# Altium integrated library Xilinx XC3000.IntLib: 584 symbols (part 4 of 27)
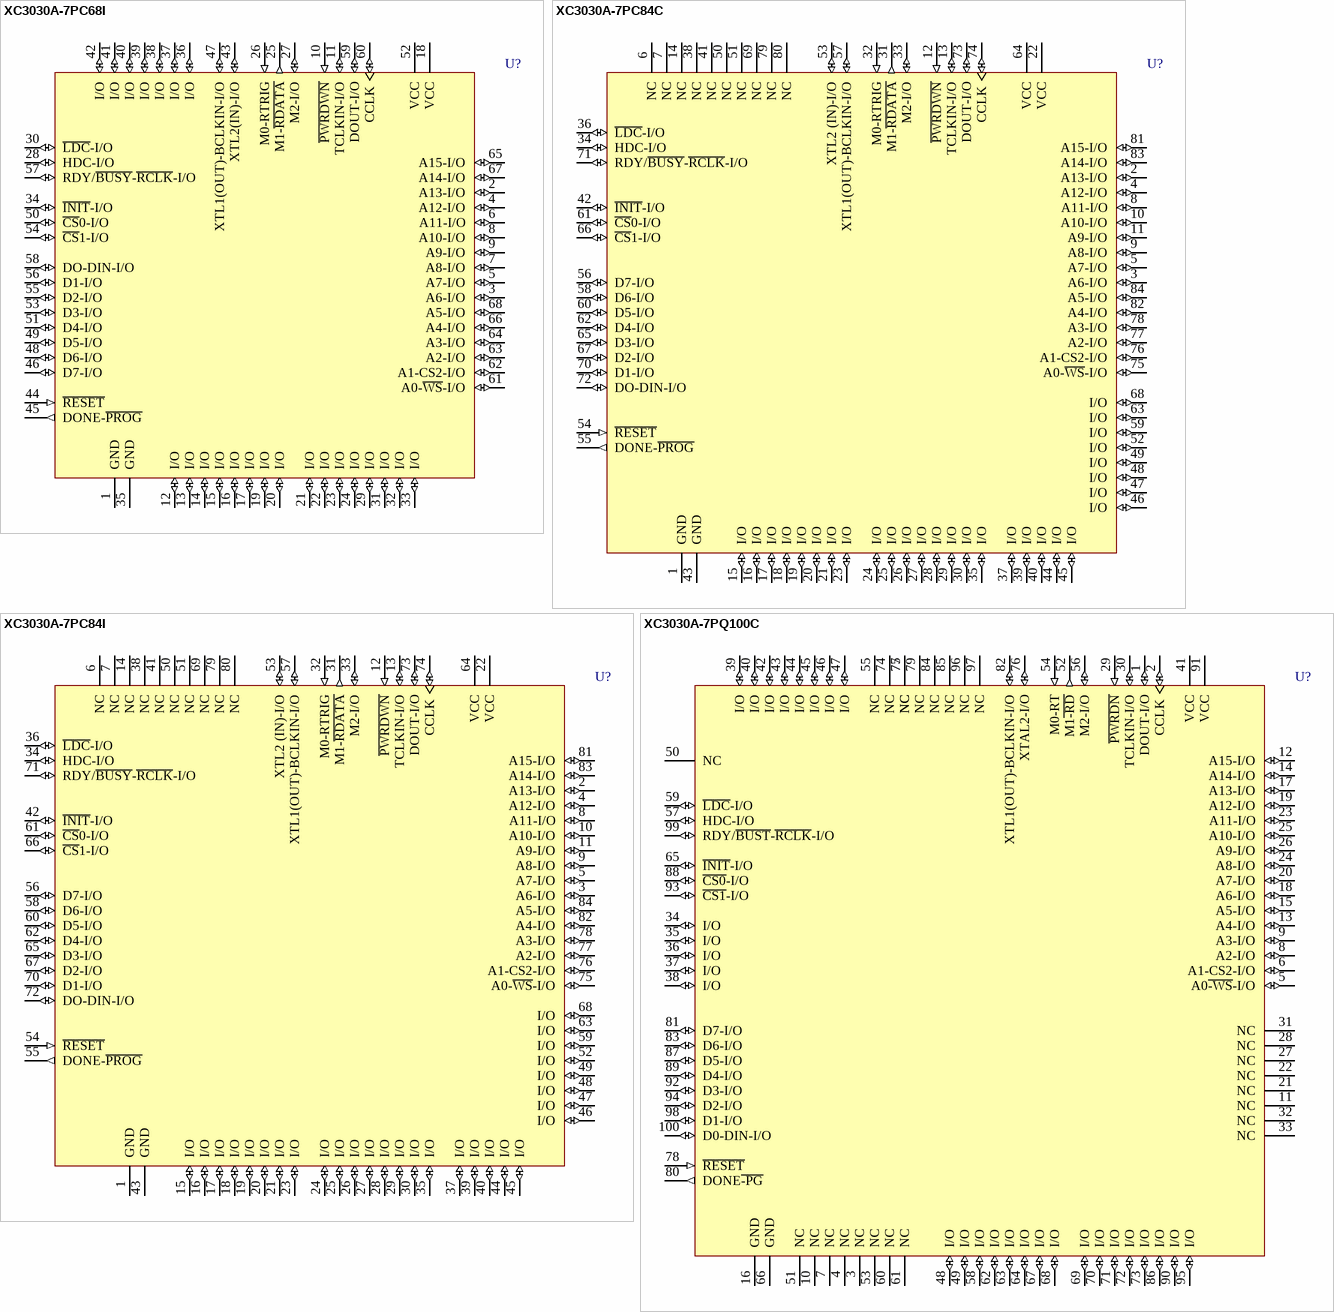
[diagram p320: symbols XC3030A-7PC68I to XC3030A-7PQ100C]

## XC3030A-7PC84C
designator U?
Logic Cell Array with 100 CLBs, with 64 I/O Pins, 84-Pin PLCC, Commercial Grade; ComponentAvailability: Not for New Design
footprint PC84_N (Leaded Chip Carrier, 84-Leads, Body 29.3x29.3mm, Pitch 1.27mm, IPC Medium Density)
footprint PC84_L (Leaded Chip Carrier, 84-Leads, Body 29.3x29.3mm, Pitch 1.27mm, IPC High Density)
footprint PC84_M (Leaded Chip Carrier, 84-Leads, Body 29.3x29.3mm, Pitch 1.27mm, IPC Low Density)
3D model XC3030A-PC84 (84-Pin Plastic Leaded Chip Carrier (PC84))
pins: 1 GND (power), 2 A13-I/O (io), 3 A6-I/O (io), 4 A12-I/O (io), 5 A7-I/O (io), 6 NC, 7 NC, 8 A11-I/O (io), 9 A8-I/O (io), 10 A10-I/O (io), 11 A9-I/O (io), 12 ~{PWRDWN} (in), 13 TCLKIN-I/O (io), 14 NC, 15 I/O (io), 16 I/O (io), 17 I/O (io), 18 I/O (io), 19 I/O (io), 20 I/O (io), 21 I/O (io), 22 VCC (power), 23 I/O (io), 24 I/O (io), 25 I/O (io), 26 I/O (io), 27 I/O (io), 28 I/O (io), 29 I/O (io), 30 I/O (io), 31 M1-~{RDATA} (out), 32 M0-RTRIG (in), 33 M2-I/O (io), 34 HDC-I/O (io), 35 I/O (io), 36 ~{LDC}-I/O (io), 37 I/O (io), 38 NC, 39 I/O (io), 40 I/O (io), 41 NC, 42 ~{INIT}-I/O (io), 43 GND (power), 44 I/O (io), 45 I/O (io), 46 I/O (io), 47 I/O (io), 48 I/O (io), 49 I/O (io), 50 NC, 51 NC, 52 I/O (io), 53 XTL2 (IN)-I/O (io), 54 ~{RESET} (in), 55 DONE-~{PROG} (out), 56 D7-I/O (io), 57 XTL1(OUT)-BCLKIN-I/O (io), 58 D6-I/O (io), 59 I/O (io), 60 D5-I/O (io), 61 ~{CS}0-I/O (io), 62 D4-I/O (io), 63 I/O (io), 64 VCC (power), 65 D3-I/O (io), 66 ~{CS}1-I/O (io), 67 D2-I/O (io), 68 I/O (io), 69 NC, 70 D1-I/O (io), 71 RDY/~{BUSY}-~{RCLK}-I/O (io), 72 DO-DIN-I/O (io), 73 DOUT-I/O (io), 74 CCLK (io), 75 A0-~{WS}-I/O (io), 76 A1-CS2-I/O (io), 77 A2-I/O (io), 78 A3-I/O (io), 79 NC, 80 NC, 81 A15-I/O (io), 82 A4-I/O (io), 83 A14-I/O (io), 84 A5-I/O (io)

## XC3030A-7PC84I
designator U?
Logic Cell Array with 100 CLBs, with 64 I/O Pins, 84-Pin PLCC, Industrial Grade; ComponentAvailability: Not for New Design
footprint PC84_N (Leaded Chip Carrier, 84-Leads, Body 29.3x29.3mm, Pitch 1.27mm, IPC Medium Density)
footprint PC84_L (Leaded Chip Carrier, 84-Leads, Body 29.3x29.3mm, Pitch 1.27mm, IPC High Density)
footprint PC84_M (Leaded Chip Carrier, 84-Leads, Body 29.3x29.3mm, Pitch 1.27mm, IPC Low Density)
3D model XC3030A-PC84 (84-Pin Plastic Leaded Chip Carrier (PC84))
pins: 1 GND (power), 2 A13-I/O (io), 3 A6-I/O (io), 4 A12-I/O (io), 5 A7-I/O (io), 6 NC, 7 NC, 8 A11-I/O (io), 9 A8-I/O (io), 10 A10-I/O (io), 11 A9-I/O (io), 12 ~{PWRDWN} (in), 13 TCLKIN-I/O (io), 14 NC, 15 I/O (io), 16 I/O (io), 17 I/O (io), 18 I/O (io), 19 I/O (io), 20 I/O (io), 21 I/O (io), 22 VCC (power), 23 I/O (io), 24 I/O (io), 25 I/O (io), 26 I/O (io), 27 I/O (io), 28 I/O (io), 29 I/O (io), 30 I/O (io), 31 M1-~{RDATA} (out), 32 M0-RTRIG (in), 33 M2-I/O (io), 34 HDC-I/O (io), 35 I/O (io), 36 ~{LDC}-I/O (io), 37 I/O (io), 38 NC, 39 I/O (io), 40 I/O (io), 41 NC, 42 ~{INIT}-I/O (io), 43 GND (power), 44 I/O (io), 45 I/O (io), 46 I/O (io), 47 I/O (io), 48 I/O (io), 49 I/O (io), 50 NC, 51 NC, 52 I/O (io), 53 XTL2 (IN)-I/O (io), 54 ~{RESET} (in), 55 DONE-~{PROG} (out), 56 D7-I/O (io), 57 XTL1(OUT)-BCLKIN-I/O (io), 58 D6-I/O (io), 59 I/O (io), 60 D5-I/O (io), 61 ~{CS}0-I/O (io), 62 D4-I/O (io), 63 I/O (io), 64 VCC (power), 65 D3-I/O (io), 66 ~{CS}1-I/O (io), 67 D2-I/O (io), 68 I/O (io), 69 NC, 70 D1-I/O (io), 71 RDY/~{BUSY}-~{RCLK}-I/O (io), 72 DO-DIN-I/O (io), 73 DOUT-I/O (io), 74 CCLK (io), 75 A0-~{WS}-I/O (io), 76 A1-CS2-I/O (io), 77 A2-I/O (io), 78 A3-I/O (io), 79 NC, 80 NC, 81 A15-I/O (io), 82 A4-I/O (io), 83 A14-I/O (io), 84 A5-I/O (io)

## XC3030A-7PQ100C
designator U?
Logic Cell Array with 100 CLBs, with 64 I/O Pins, 100-Pin PQFP, Commercial Grade; ComponentAvailability: Not for New Design
footprint PQ100_N (QFP, 100-Leads, Body 20x14mm, Pitch 0.65mm, IPC Medium Density)
footprint PQ100_L (QFP, 100-Leads, Body 20x14mm, Pitch 0.65mm, IPC High Density)
footprint PQ100_M (QFP, 100-Leads, Body 20x14mm, Pitch 0.65mm, IPC Low Density)
3D model XC3030A-PQ100 (100-Pin Plastic Quad Flat Pack (PQ100))
pins: 1 DOUT-I/O (io), 2 CCLK (io), 3 NC, 4 NC, 5 A0~{-WS}-I/O (io), 6 A1-CS2-I/O (io), 7 NC, 8 A2-I/O (io), 9 A3-I/O (io), 10 NC, 11 NC, 12 A15-I/O (io), 13 A4-I/O (io), 14 A14-I/O (io), 15 A5-I/O (io), 16 GND (power), 17 A13-I/O (io), 18 A6-I/O (io), 19 A12-I/O (io), 20 A7-I/O (io), 21 NC, 22 NC, 23 A11-I/O (io), 24 A8-I/O (io), 25 A10-I/O (io), 26 A9-I/O (io), 27 NC, 28 NC, 29 ~{PWRDN} (in), 30 TCLKIN-I/O (io), 31 NC, 32 NC, 33 NC, 34 I/O (io), 35 I/O (io), 36 I/O (io), 37 I/O (io), 38 I/O (io), 39 I/O (io), 40 I/O (io), 41 VCC (power), 42 I/O (io), 43 I/O (io), 44 I/O (io), 45 I/O (io), 46 I/O (io), 47 I/O (io), 48 I/O (io), 49 I/O (io), 50 NC, 51 NC, 52 M1~{-RD} (out), 53 NC, 54 M0-RT (in), 55 NC, 56 M2-I/O (io), 57 HDC-I/O (io), 58 I/O (io), 59 ~{LDC}-I/O (io), 60 NC, 61 NC, 62 I/O (io), 63 I/O (io), 64 I/O (io), 65 ~{INIT}-I/O (io), 66 GND (power), 67 I/O (io), 68 I/O (io), 69 I/O (io), 70 I/O (io), 71 I/O (io), 72 I/O (io), 73 I/O (io), 74 NC, 75 NC, 76 XTAL2-I/O (io), 77 NC, 78 ~{RESET} (in), 79 NC, 80 DONE~{-PG} (out), 81 D7-I/O (io), 82 XTL1(OUT)-BCLKIN-I/O (io), 83 D6-I/O (io), 84 NC, 85 NC, 86 I/O (io), 87 D5-I/O (io), 88 ~{CS0}-I/O (io), 89 D4-I/O (io), 90 I/O (io), 91 VCC (power), 92 D3-I/O (io), 93 ~{CS1}-I/O (io), 94 D2-I/O (io), 95 I/O (io), 96 NC, 97 NC, 98 D1-I/O (io), 99 RDY/~{BUST}-~{RCLK}-I/O (io), 100 D0-DIN-I/O (io)

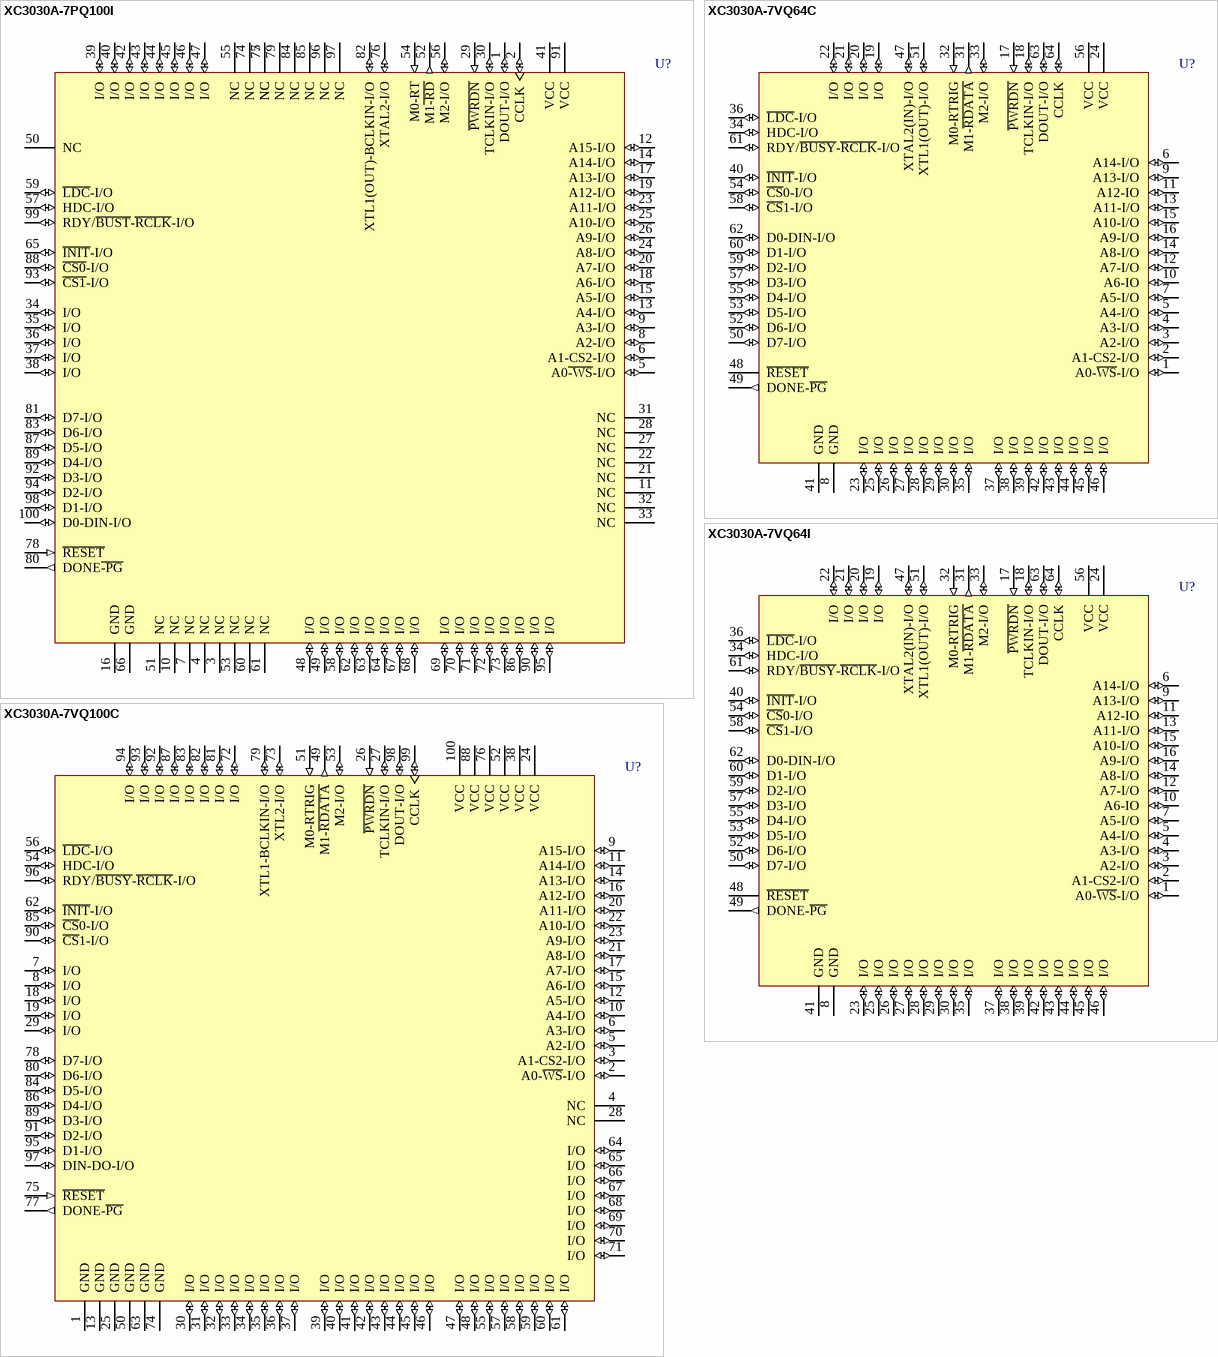
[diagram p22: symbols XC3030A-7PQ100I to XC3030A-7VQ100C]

## XC3030A-7PQ100I
designator U?
Logic Cell Array with 100 CLBs, with 64 I/O Pins, 100-Pin PQFP, Industrial Grade; ComponentAvailability: Not for New Design
footprint PQ100_N (QFP, 100-Leads, Body 20x14mm, Pitch 0.65mm, IPC Medium Density)
footprint PQ100_L (QFP, 100-Leads, Body 20x14mm, Pitch 0.65mm, IPC High Density)
footprint PQ100_M (QFP, 100-Leads, Body 20x14mm, Pitch 0.65mm, IPC Low Density)
3D model XC3030A-PQ100 (100-Pin Plastic Quad Flat Pack (PQ100))
pins: 1 DOUT-I/O (io), 2 CCLK (io), 3 NC, 4 NC, 5 A0~{-WS}-I/O (io), 6 A1-CS2-I/O (io), 7 NC, 8 A2-I/O (io), 9 A3-I/O (io), 10 NC, 11 NC, 12 A15-I/O (io), 13 A4-I/O (io), 14 A14-I/O (io), 15 A5-I/O (io), 16 GND (power), 17 A13-I/O (io), 18 A6-I/O (io), 19 A12-I/O (io), 20 A7-I/O (io), 21 NC, 22 NC, 23 A11-I/O (io), 24 A8-I/O (io), 25 A10-I/O (io), 26 A9-I/O (io), 27 NC, 28 NC, 29 ~{PWRDN} (in), 30 TCLKIN-I/O (io), 31 NC, 32 NC, 33 NC, 34 I/O (io), 35 I/O (io), 36 I/O (io), 37 I/O (io), 38 I/O (io), 39 I/O (io), 40 I/O (io), 41 VCC (power), 42 I/O (io), 43 I/O (io), 44 I/O (io), 45 I/O (io), 46 I/O (io), 47 I/O (io), 48 I/O (io), 49 I/O (io), 50 NC, 51 NC, 52 M1~{-RD} (out), 53 NC, 54 M0-RT (in), 55 NC, 56 M2-I/O (io), 57 HDC-I/O (io), 58 I/O (io), 59 ~{LDC}-I/O (io), 60 NC, 61 NC, 62 I/O (io), 63 I/O (io), 64 I/O (io), 65 ~{INIT}-I/O (io), 66 GND (power), 67 I/O (io), 68 I/O (io), 69 I/O (io), 70 I/O (io), 71 I/O (io), 72 I/O (io), 73 I/O (io), 74 NC, 75 NC, 76 XTAL2-I/O (io), 77 NC, 78 ~{RESET} (in), 79 NC, 80 DONE~{-PG} (out), 81 D7-I/O (io), 82 XTL1(OUT)-BCLKIN-I/O (io), 83 D6-I/O (io), 84 NC, 85 NC, 86 I/O (io), 87 D5-I/O (io), 88 ~{CS0}-I/O (io), 89 D4-I/O (io), 90 I/O (io), 91 VCC (power), 92 D3-I/O (io), 93 ~{CS1}-I/O (io), 94 D2-I/O (io), 95 I/O (io), 96 NC, 97 NC, 98 D1-I/O (io), 99 RDY/~{BUST}-~{RCLK}-I/O (io), 100 D0-DIN-I/O (io)

## XC3030A-7VQ64C
designator U?
Logic Cell Array with 100 CLBs, with 54 I/O Pins, 64-Pin VQFP, Commercial Grade; ComponentAvailability: Not for New Design
footprint VQ64_N (Thin QFP, 64-Leads, Body 10x10mm, Pitch 0.5mm, IPC Medium Density)
footprint VQ64_L (Thin QFP, 64-Leads, Body 10x10mm, Pitch 0.5mm, IPC High Density)
footprint VQ64_M (Thin QFP, 64-Leads, Body 10x10mm, Pitch 0.5mm, IPC Low Density)
3D model XC3030A-VQ64 (64-Pin Very Thin Quad Flat Pack (VQ64))
pins: 1 A0-~{WS}-I/O (io), 2 A1-CS2-I/O (io), 3 A2-I/O (io), 4 A3-I/O (io), 5 A4-I/O (io), 6 A14-I/O (io), 7 A5-I/O (io), 8 GND (power), 9 A13-I/O (io), 10 A6-IO (io), 11 A12-IO (io), 12 A7-I/O (io), 13 A11-I/O (io), 14 A8-I/O (io), 15 A10-I/O (io), 16 A9-I/O (io), 17 ~{PWRDN} (in), 18 TCLKIN-I/O (io), 19 I/O (io), 20 I/O (io), 21 I/O (io), 22 I/O (io), 23 I/O (io), 24 VCC (power), 25 I/O (io), 26 I/O (io), 27 I/O (io), 28 I/O (io), 29 I/O (io), 30 I/O (io), 31 M1-~{RDATA} (out), 32 M0-RTRIG (in), 33 M2-I/O (io), 34 HDC-I/O (io), 35 I/O (io), 36 ~{LDC}-I/O (io), 37 I/O (io), 38 I/O (io), 39 I/O (io), 40 ~{INIT}-I/O (io), 41 GND (power), 42 I/O (io), 43 I/O (io), 44 I/O (io), 45 I/O (io), 46 I/O (io), 47 XTAL2(IN)-I/O (io), 48 ~{RESET}, 49 DONE-~{PG} (out), 50 D7-I/O (io), 51 XTL1(OUT)-I/O (io), 52 D6-I/O (io), 53 D5-I/O (io), 54 ~{CS}0-I/O (io), 55 D4-I/O (io), 56 VCC (power), 57 D3-I/O (io), 58 ~{CS}1-I/O (io), 59 D2-I/O (io), 60 D1-I/O (io), 61 RDY/~{BUSY}-~{RCLK}-I/O (io), 62 D0-DIN-I/O (io), 63 DOUT-I/O (io), 64 CCLK (io)

## XC3030A-7VQ64I
designator U?
Logic Cell Array with 100 CLBs, with 54 I/O Pins, 64-Pin VQFP, Industrial Grade; ComponentAvailability: Not for New Design
footprint VQ64_N (Thin QFP, 64-Leads, Body 10x10mm, Pitch 0.5mm, IPC Medium Density)
footprint VQ64_L (Thin QFP, 64-Leads, Body 10x10mm, Pitch 0.5mm, IPC High Density)
footprint VQ64_M (Thin QFP, 64-Leads, Body 10x10mm, Pitch 0.5mm, IPC Low Density)
3D model XC3030A-VQ64 (64-Pin Very Thin Quad Flat Pack (VQ64))
pins: 1 A0-~{WS}-I/O (io), 2 A1-CS2-I/O (io), 3 A2-I/O (io), 4 A3-I/O (io), 5 A4-I/O (io), 6 A14-I/O (io), 7 A5-I/O (io), 8 GND (power), 9 A13-I/O (io), 10 A6-IO (io), 11 A12-IO (io), 12 A7-I/O (io), 13 A11-I/O (io), 14 A8-I/O (io), 15 A10-I/O (io), 16 A9-I/O (io), 17 ~{PWRDN} (in), 18 TCLKIN-I/O (io), 19 I/O (io), 20 I/O (io), 21 I/O (io), 22 I/O (io), 23 I/O (io), 24 VCC (power), 25 I/O (io), 26 I/O (io), 27 I/O (io), 28 I/O (io), 29 I/O (io), 30 I/O (io), 31 M1-~{RDATA} (out), 32 M0-RTRIG (in), 33 M2-I/O (io), 34 HDC-I/O (io), 35 I/O (io), 36 ~{LDC}-I/O (io), 37 I/O (io), 38 I/O (io), 39 I/O (io), 40 ~{INIT}-I/O (io), 41 GND (power), 42 I/O (io), 43 I/O (io), 44 I/O (io), 45 I/O (io), 46 I/O (io), 47 XTAL2(IN)-I/O (io), 48 ~{RESET}, 49 DONE-~{PG} (out), 50 D7-I/O (io), 51 XTL1(OUT)-I/O (io), 52 D6-I/O (io), 53 D5-I/O (io), 54 ~{CS}0-I/O (io), 55 D4-I/O (io), 56 VCC (power), 57 D3-I/O (io), 58 ~{CS}1-I/O (io), 59 D2-I/O (io), 60 D1-I/O (io), 61 RDY/~{BUSY}-~{RCLK}-I/O (io), 62 D0-DIN-I/O (io), 63 DOUT-I/O (io), 64 CCLK (io)

## XC3030A-7VQ100C
designator U?
Logic Cell Array with 100 CLBs, with 80 I/O Pins, 100-Pin VQFP, Commercial Grade; ComponentAvailability: Not for New Design
footprint VQ100_N (Thin QFP, 100-Leads, Body 14x14mm, Pitch 0.5mm, IPC Medium Density)
footprint VQ100_L (Thin QFP, 100-Leads, Body 14x14mm, Pitch 0.5mm, IPC High Density)
footprint VQ100_M (Thin QFP, 100-Leads, Body 14x14mm, Pitch 0.5mm, IPC Low Density)
3D model XC3030A-VQ100 (100-Pin Very Thin Quad Flat Pack (VQ100))
pins: 1 GND (power), 2 A0-~{WS}-I/O (io), 3 A1-CS2-I/O (io), 4 NC, 5 A2-I/O (io), 6 A3-I/O (io), 7 I/O (io), 8 I/O (io), 9 A15-I/O (io), 10 A4-I/O (io), 11 A14-I/O (io), 12 A5-I/O (io), 13 GND (power), 14 A13-I/O (io), 15 A6-I/O (io), 16 A12-I/O (io), 17 A7-I/O (io), 18 I/O (io), 19 I/O (io), 20 A11-I/O (io), 21 A8-I/O (io), 22 A10-I/O (io), 23 A9-I/O (io), 24 VCC (power), 25 GND (power), 26 ~{PWRDN} (in), 27 TCLKIN-I/O (io), 28 NC, 29 I/O (io), 30 I/O (io), 31 I/O (io), 32 I/O (io), 33 I/O (io), 34 I/O (io), 35 I/O (io), 36 I/O (io), 37 I/O (io), 38 VCC (power), 39 I/O (io), 40 I/O (io), 41 I/O (io), 42 I/O (io), 43 I/O (io), 44 I/O (io), 45 I/O (io), 46 I/O (io), 47 I/O (io), 48 I/O (io), 49 M1-~{RDATA} (out), 50 GND (power), 51 M0-RTRIG (in), 52 VCC (power), 53 M2-I/O (io), 54 HDC-I/O (io), 55 I/O (io), 56 ~{LDC}-I/O (io), 57 I/O (io), 58 I/O (io), 59 I/O (io), 60 I/O (io), 61 I/O (io), 62 ~{INIT}-I/O (io), 63 GND (power), 64 I/O (io), 65 I/O (io), 66 I/O (io), 67 I/O (io), 68 I/O (io), 69 I/O (io), 70 I/O (io), 71 I/O (io), 72 I/O (io), 73 XTL2-I/O (io), 74 GND (power), 75 ~{RESET} (in), 76 VCC (power), 77 DONE-~{PG} (out), 78 D7-I/O (io), 79 XTL1-BCLKIN-I/O (io), 80 D6-I/O (io), 81 I/O (io), 82 I/O (io), 83 I/O (io), 84 D5-I/O (io), 85 ~{CS}0-I/O (io), 86 D4-I/O (io), 87 I/O (io), 88 VCC (power), 89 D3-I/O (io), 90 ~{CS}1-I/O (io), 91 D2-I/O (io), 92 I/O (io), 93 I/O (io), 94 I/O (io), 95 D1-I/O (io), 96 RDY/~{BUSY}-~{RCLK}-I/O (io), 97 DIN-DO-I/O (io), 98 DOUT-I/O (io), 99 CCLK (io), 100 VCC (power)

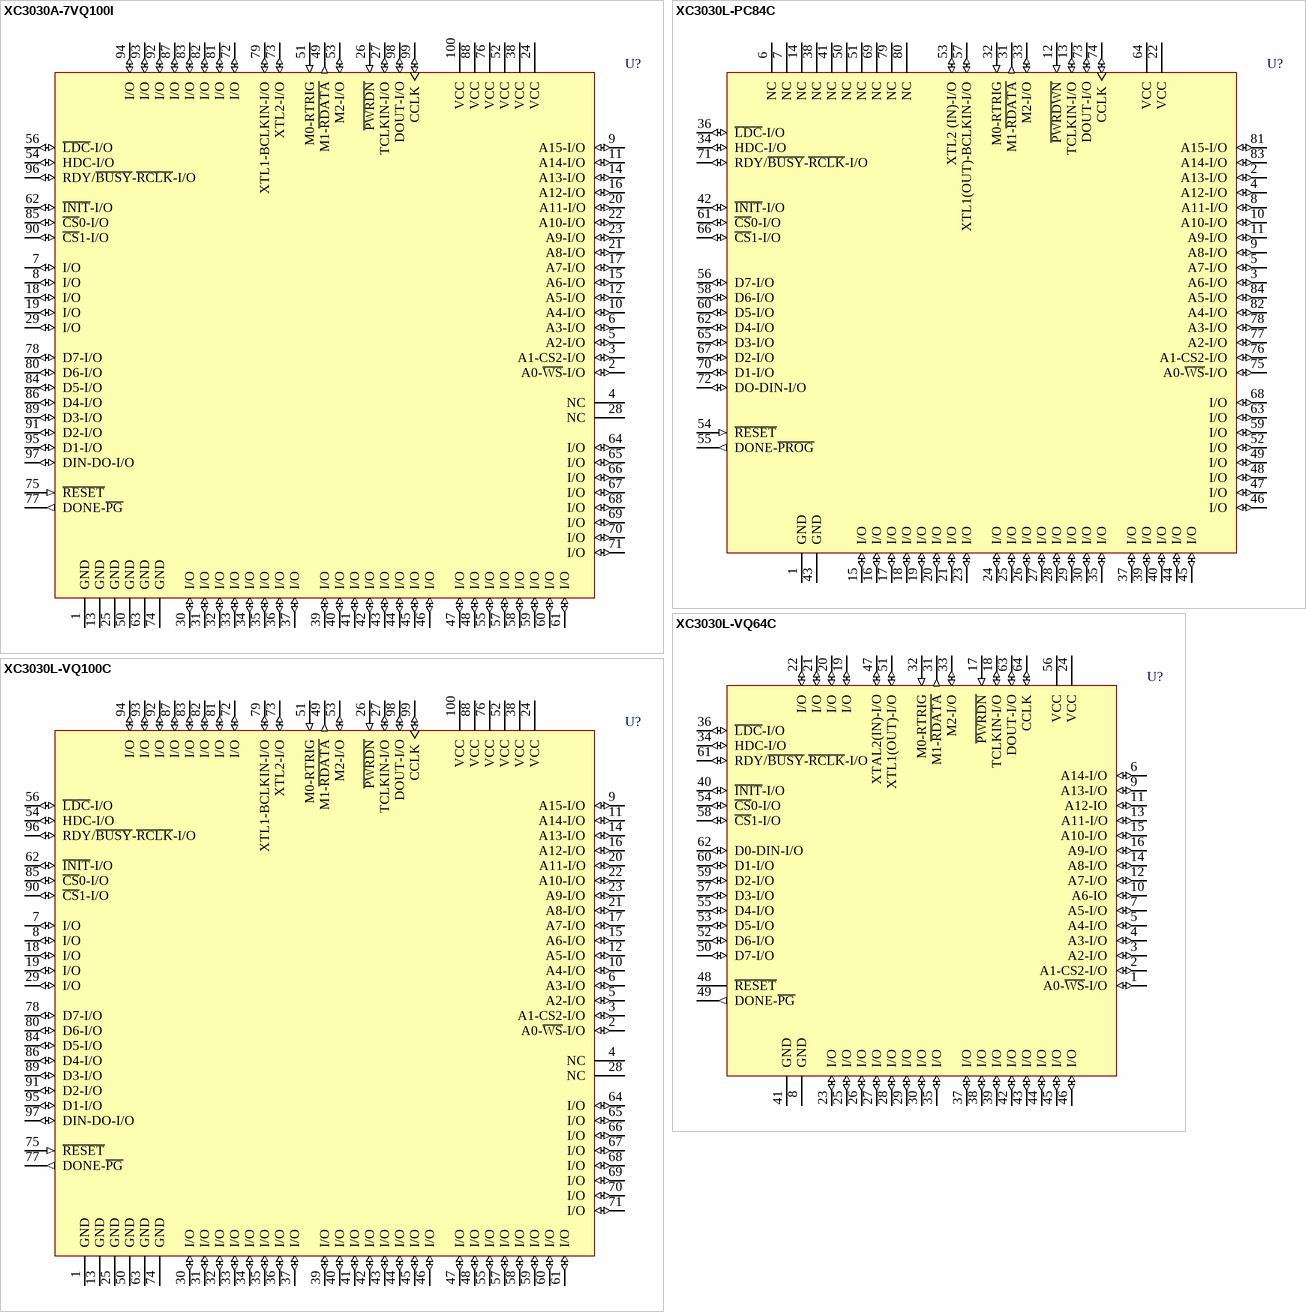
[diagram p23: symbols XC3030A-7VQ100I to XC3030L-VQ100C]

## XC3030A-7VQ100I
designator U?
Logic Cell Array with 100 CLBs, with 80 I/O Pins, 100-Pin VQFP, Industrial Grade; ComponentAvailability: Not for New Design
footprint VQ100_N (Thin QFP, 100-Leads, Body 14x14mm, Pitch 0.5mm, IPC Medium Density)
footprint VQ100_L (Thin QFP, 100-Leads, Body 14x14mm, Pitch 0.5mm, IPC High Density)
footprint VQ100_M (Thin QFP, 100-Leads, Body 14x14mm, Pitch 0.5mm, IPC Low Density)
3D model XC3030A-VQ100 (100-Pin Very Thin Quad Flat Pack (VQ100))
pins: 1 GND (power), 2 A0-~{WS}-I/O (io), 3 A1-CS2-I/O (io), 4 NC, 5 A2-I/O (io), 6 A3-I/O (io), 7 I/O (io), 8 I/O (io), 9 A15-I/O (io), 10 A4-I/O (io), 11 A14-I/O (io), 12 A5-I/O (io), 13 GND (power), 14 A13-I/O (io), 15 A6-I/O (io), 16 A12-I/O (io), 17 A7-I/O (io), 18 I/O (io), 19 I/O (io), 20 A11-I/O (io), 21 A8-I/O (io), 22 A10-I/O (io), 23 A9-I/O (io), 24 VCC (power), 25 GND (power), 26 ~{PWRDN} (in), 27 TCLKIN-I/O (io), 28 NC, 29 I/O (io), 30 I/O (io), 31 I/O (io), 32 I/O (io), 33 I/O (io), 34 I/O (io), 35 I/O (io), 36 I/O (io), 37 I/O (io), 38 VCC (power), 39 I/O (io), 40 I/O (io), 41 I/O (io), 42 I/O (io), 43 I/O (io), 44 I/O (io), 45 I/O (io), 46 I/O (io), 47 I/O (io), 48 I/O (io), 49 M1-~{RDATA} (out), 50 GND (power), 51 M0-RTRIG (in), 52 VCC (power), 53 M2-I/O (io), 54 HDC-I/O (io), 55 I/O (io), 56 ~{LDC}-I/O (io), 57 I/O (io), 58 I/O (io), 59 I/O (io), 60 I/O (io), 61 I/O (io), 62 ~{INIT}-I/O (io), 63 GND (power), 64 I/O (io), 65 I/O (io), 66 I/O (io), 67 I/O (io), 68 I/O (io), 69 I/O (io), 70 I/O (io), 71 I/O (io), 72 I/O (io), 73 XTL2-I/O (io), 74 GND (power), 75 ~{RESET} (in), 76 VCC (power), 77 DONE-~{PG} (out), 78 D7-I/O (io), 79 XTL1-BCLKIN-I/O (io), 80 D6-I/O (io), 81 I/O (io), 82 I/O (io), 83 I/O (io), 84 D5-I/O (io), 85 ~{CS}0-I/O (io), 86 D4-I/O (io), 87 I/O (io), 88 VCC (power), 89 D3-I/O (io), 90 ~{CS}1-I/O (io), 91 D2-I/O (io), 92 I/O (io), 93 I/O (io), 94 I/O (io), 95 D1-I/O (io), 96 RDY/~{BUSY}-~{RCLK}-I/O (io), 97 DIN-DO-I/O (io), 98 DOUT-I/O (io), 99 CCLK (io), 100 VCC (power)

## XC3030L-PC84C
designator U?
Logic Cell Array with 100 CLBs, with 64 I/O Pins, 84-Pin PLCC, Commercial Grade; ComponentAvailability: Not for New Design
footprint PC84_N (Leaded Chip Carrier, 84-Leads, Body 29.3x29.3mm, Pitch 1.27mm, IPC Medium Density)
footprint PC84_L (Leaded Chip Carrier, 84-Leads, Body 29.3x29.3mm, Pitch 1.27mm, IPC High Density)
footprint PC84_M (Leaded Chip Carrier, 84-Leads, Body 29.3x29.3mm, Pitch 1.27mm, IPC Low Density)
3D model XC3030L-PC84 (84-Pin Plastic Leaded Chip Carrier (PC84))
pins: 1 GND (power), 2 A13-I/O (io), 3 A6-I/O (io), 4 A12-I/O (io), 5 A7-I/O (io), 6 NC, 7 NC, 8 A11-I/O (io), 9 A8-I/O (io), 10 A10-I/O (io), 11 A9-I/O (io), 12 ~{PWRDWN} (in), 13 TCLKIN-I/O (io), 14 NC, 15 I/O (io), 16 I/O (io), 17 I/O (io), 18 I/O (io), 19 I/O (io), 20 I/O (io), 21 I/O (io), 22 VCC (power), 23 I/O (io), 24 I/O (io), 25 I/O (io), 26 I/O (io), 27 I/O (io), 28 I/O (io), 29 I/O (io), 30 I/O (io), 31 M1-~{RDATA} (out), 32 M0-RTRIG (in), 33 M2-I/O (io), 34 HDC-I/O (io), 35 I/O (io), 36 ~{LDC}-I/O (io), 37 I/O (io), 38 NC, 39 I/O (io), 40 I/O (io), 41 NC, 42 ~{INIT}-I/O (io), 43 GND (power), 44 I/O (io), 45 I/O (io), 46 I/O (io), 47 I/O (io), 48 I/O (io), 49 I/O (io), 50 NC, 51 NC, 52 I/O (io), 53 XTL2 (IN)-I/O (io), 54 ~{RESET} (in), 55 DONE-~{PROG} (out), 56 D7-I/O (io), 57 XTL1(OUT)-BCLKIN-I/O (io), 58 D6-I/O (io), 59 I/O (io), 60 D5-I/O (io), 61 ~{CS}0-I/O (io), 62 D4-I/O (io), 63 I/O (io), 64 VCC (power), 65 D3-I/O (io), 66 ~{CS}1-I/O (io), 67 D2-I/O (io), 68 I/O (io), 69 NC, 70 D1-I/O (io), 71 RDY/~{BUSY}-~{RCLK}-I/O (io), 72 DO-DIN-I/O (io), 73 DOUT-I/O (io), 74 CCLK (io), 75 A0-~{WS}-I/O (io), 76 A1-CS2-I/O (io), 77 A2-I/O (io), 78 A3-I/O (io), 79 NC, 80 NC, 81 A15-I/O (io), 82 A4-I/O (io), 83 A14-I/O (io), 84 A5-I/O (io)

## XC3030L-VQ64C
designator U?
Logic Cell Array with 100 CLBs, with 54 I/O Pins, 64-Pin VQFP, Commercial Grade; ComponentAvailability: Not for New Design
footprint VQ64_N (Thin QFP, 64-Leads, Body 10x10mm, Pitch 0.5mm, IPC Medium Density)
footprint VQ64_L (Thin QFP, 64-Leads, Body 10x10mm, Pitch 0.5mm, IPC High Density)
footprint VQ64_M (Thin QFP, 64-Leads, Body 10x10mm, Pitch 0.5mm, IPC Low Density)
3D model XC3030L-VQ64 (64-Pin Very Thin Quad Flat Pack (VQ64))
pins: 1 A0-~{WS}-I/O (io), 2 A1-CS2-I/O (io), 3 A2-I/O (io), 4 A3-I/O (io), 5 A4-I/O (io), 6 A14-I/O (io), 7 A5-I/O (io), 8 GND (power), 9 A13-I/O (io), 10 A6-IO (io), 11 A12-IO (io), 12 A7-I/O (io), 13 A11-I/O (io), 14 A8-I/O (io), 15 A10-I/O (io), 16 A9-I/O (io), 17 ~{PWRDN} (in), 18 TCLKIN-I/O (io), 19 I/O (io), 20 I/O (io), 21 I/O (io), 22 I/O (io), 23 I/O (io), 24 VCC (power), 25 I/O (io), 26 I/O (io), 27 I/O (io), 28 I/O (io), 29 I/O (io), 30 I/O (io), 31 M1-~{RDATA} (out), 32 M0-RTRIG (in), 33 M2-I/O (io), 34 HDC-I/O (io), 35 I/O (io), 36 ~{LDC}-I/O (io), 37 I/O (io), 38 I/O (io), 39 I/O (io), 40 ~{INIT}-I/O (io), 41 GND (power), 42 I/O (io), 43 I/O (io), 44 I/O (io), 45 I/O (io), 46 I/O (io), 47 XTAL2(IN)-I/O (io), 48 ~{RESET}, 49 DONE-~{PG} (out), 50 D7-I/O (io), 51 XTL1(OUT)-I/O (io), 52 D6-I/O (io), 53 D5-I/O (io), 54 ~{CS}0-I/O (io), 55 D4-I/O (io), 56 VCC (power), 57 D3-I/O (io), 58 ~{CS}1-I/O (io), 59 D2-I/O (io), 60 D1-I/O (io), 61 RDY/~{BUSY}-~{RCLK}-I/O (io), 62 D0-DIN-I/O (io), 63 DOUT-I/O (io), 64 CCLK (io)

## XC3030L-VQ100C
designator U?
Logic Cell Array with 100 CLBs, with 80 I/O Pins, 100-Pin VQFP, Commercial Grade; ComponentAvailability: Not for New Design
footprint VQ100_N (Thin QFP, 100-Leads, Body 14x14mm, Pitch 0.5mm, IPC Medium Density)
footprint VQ100_L (Thin QFP, 100-Leads, Body 14x14mm, Pitch 0.5mm, IPC High Density)
footprint VQ100_M (Thin QFP, 100-Leads, Body 14x14mm, Pitch 0.5mm, IPC Low Density)
3D model XC3030L-VQ100 (100-Pin Very Thin Quad Flat Pack (VQ100))
pins: 1 GND (power), 2 A0-~{WS}-I/O (io), 3 A1-CS2-I/O (io), 4 NC, 5 A2-I/O (io), 6 A3-I/O (io), 7 I/O (io), 8 I/O (io), 9 A15-I/O (io), 10 A4-I/O (io), 11 A14-I/O (io), 12 A5-I/O (io), 13 GND (power), 14 A13-I/O (io), 15 A6-I/O (io), 16 A12-I/O (io), 17 A7-I/O (io), 18 I/O (io), 19 I/O (io), 20 A11-I/O (io), 21 A8-I/O (io), 22 A10-I/O (io), 23 A9-I/O (io), 24 VCC (power), 25 GND (power), 26 ~{PWRDN} (in), 27 TCLKIN-I/O (io), 28 NC, 29 I/O (io), 30 I/O (io), 31 I/O (io), 32 I/O (io), 33 I/O (io), 34 I/O (io), 35 I/O (io), 36 I/O (io), 37 I/O (io), 38 VCC (power), 39 I/O (io), 40 I/O (io), 41 I/O (io), 42 I/O (io), 43 I/O (io), 44 I/O (io), 45 I/O (io), 46 I/O (io), 47 I/O (io), 48 I/O (io), 49 M1-~{RDATA} (out), 50 GND (power), 51 M0-RTRIG (in), 52 VCC (power), 53 M2-I/O (io), 54 HDC-I/O (io), 55 I/O (io), 56 ~{LDC}-I/O (io), 57 I/O (io), 58 I/O (io), 59 I/O (io), 60 I/O (io), 61 I/O (io), 62 ~{INIT}-I/O (io), 63 GND (power), 64 I/O (io), 65 I/O (io), 66 I/O (io), 67 I/O (io), 68 I/O (io), 69 I/O (io), 70 I/O (io), 71 I/O (io), 72 I/O (io), 73 XTL2-I/O (io), 74 GND (power), 75 ~{RESET} (in), 76 VCC (power), 77 DONE-~{PG} (out), 78 D7-I/O (io), 79 XTL1-BCLKIN-I/O (io), 80 D6-I/O (io), 81 I/O (io), 82 I/O (io), 83 I/O (io), 84 D5-I/O (io), 85 ~{CS}0-I/O (io), 86 D4-I/O (io), 87 I/O (io), 88 VCC (power), 89 D3-I/O (io), 90 ~{CS}1-I/O (io), 91 D2-I/O (io), 92 I/O (io), 93 I/O (io), 94 I/O (io), 95 D1-I/O (io), 96 RDY/~{BUSY}-~{RCLK}-I/O (io), 97 DIN-DO-I/O (io), 98 DOUT-I/O (io), 99 CCLK (io), 100 VCC (power)

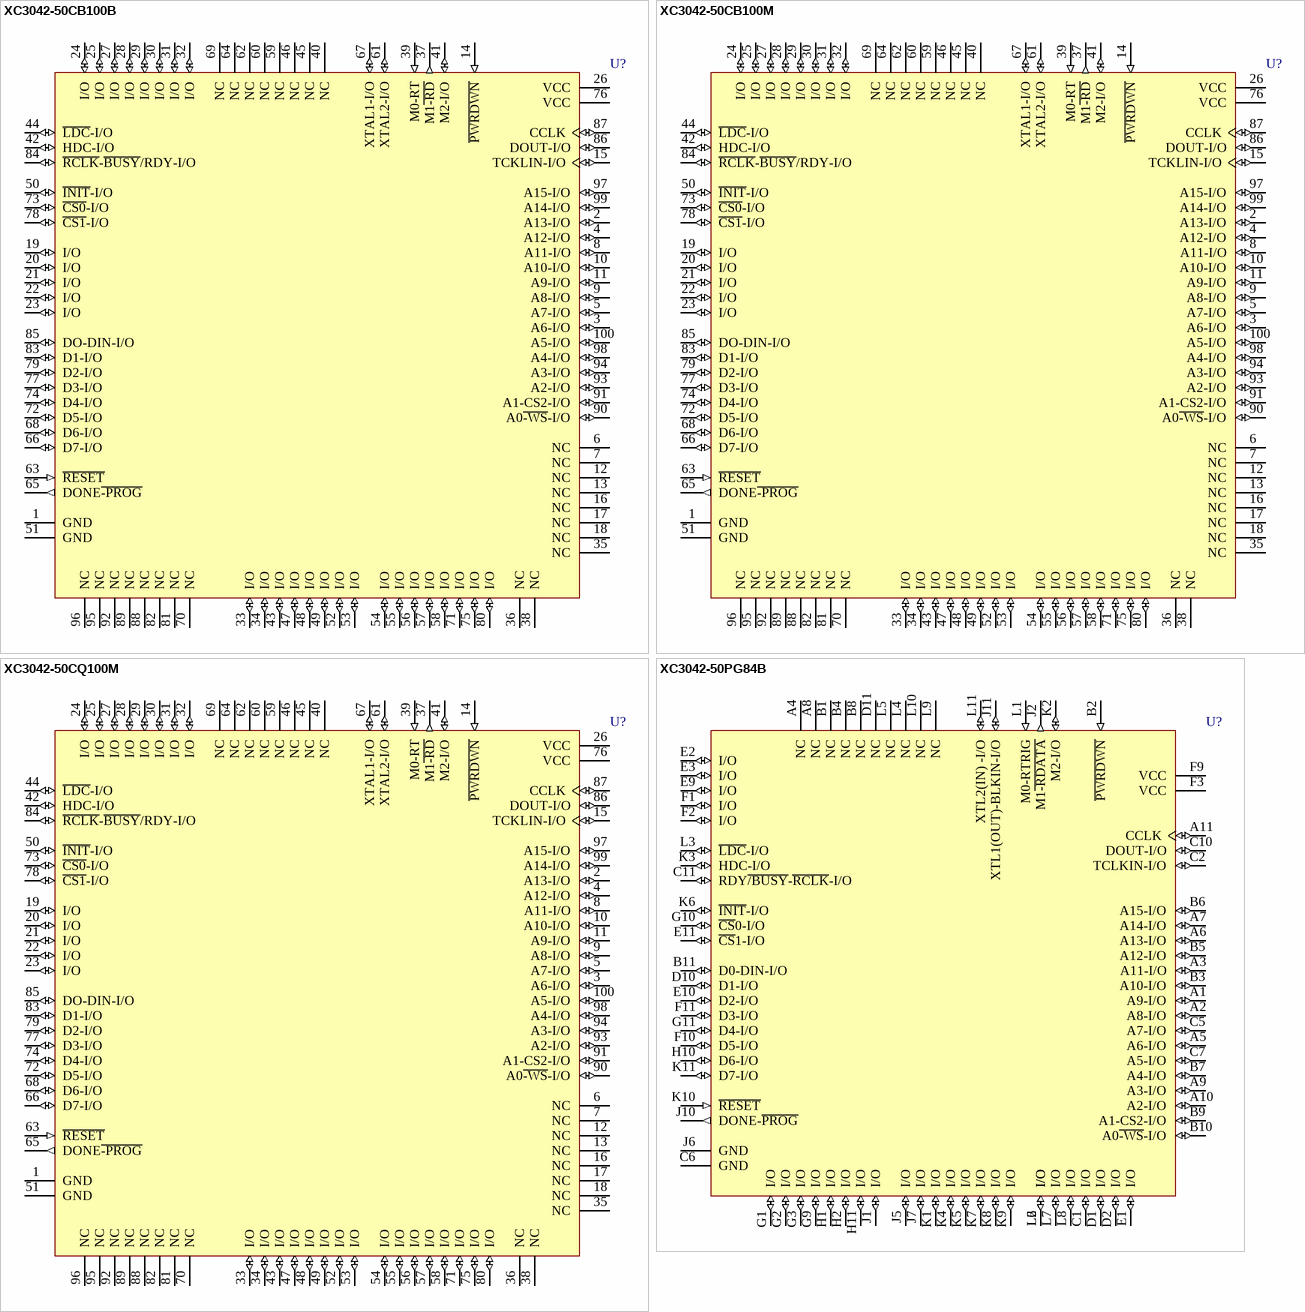
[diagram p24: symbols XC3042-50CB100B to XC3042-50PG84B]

## XC3042-50CB100B
designator U?
Logic Cell Array with 144 CLBs, with 64 I/O Pins, 100-Pin CQFP, Military Class B Grade; ComponentAvailability: Not for New Design
footprint CB100_N (CQFP, 100-Leads, Body 19x19mm; Pitch 0.635mm, Gullwing Leadform, IPC Medium Density)
footprint CB100_L (CQFP, 100-Leads, Body 19x19mm; Pitch 0.635mm, Gullwing Leadform, IPC High Density)
footprint CB100_M (CQFP, 100-Leads, Body 19x19mm; Pitch 0.635mm, Gullwing Leadform, IPC Low Density)
3D model XC3042-CB100 (100-Pin Ceramic Brazed Quad Flat Pack (CB100))
pins: 1 GND (power), 2 A13-I/O (io), 3 A6-I/O (io), 4 A12-I/O (io), 5 A7-I/O (io), 6 NC, 7 NC, 8 A11-I/O (io), 9 A8-I/O (io), 10 A10-I/O (io), 11 A9-I/O (io), 12 NC, 13 NC, 14 ~{PWRDWN} (in), 15 TCKLIN-I/O (io), 16 NC, 17 NC, 18 NC, 19 I/O (io), 20 I/O (io), 21 I/O (io), 22 I/O (io), 23 I/O (io), 24 I/O (io), 25 I/O (io), 26 VCC (power), 27 I/O (io), 28 I/O (io), 29 I/O (io), 30 I/O (io), 31 I/O (io), 32 I/O (io), 33 I/O (io), 34 I/O (io), 35 NC, 36 NC, 37 M1~{-RD} (out), 38 NC, 39 M0-RT (in), 40 NC, 41 M2-I/O (io), 42 HDC-I/O (io), 43 I/O (io), 44 ~{LDC}-I/O (io), 45 NC, 46 NC, 47 I/O (io), 48 I/O (io), 49 I/O (io), 50 ~{INIT}-I/O (io), 51 GND (power), 52 I/O (io), 53 I/O (io), 54 I/O (io), 55 I/O (io), 56 I/O (io), 57 I/O (io), 58 I/O (io), 59 NC, 60 NC, 61 XTAL2-I/O (io), 62 NC, 63 ~{RESET} (in), 64 NC, 65 DONE~{-PROG} (out), 66 D7-I/O (io), 67 XTAL1-I/O (io), 68 D6-I/O (io), 69 NC, 70 NC, 71 I/O (io), 72 D5-I/O (io), 73 ~{CS0}-I/O (io), 74 D4-I/O (io), 75 I/O (io), 76 VCC (power), 77 D3-I/O (io), 78 ~{CS1}-I/O (io), 79 D2-I/O (io), 80 I/O (io), 81 NC, 82 NC, 83 D1-I/O (io), 84 ~{RCLK}-~{BUSY}/RDY-I/O (io), 85 DO-DIN-I/O (io), 86 DOUT-I/O (io), 87 CCLK (io), 88 NC, 89 NC, 90 A0~{-WS}-I/O (io), 91 A1-CS2-I/O (io), 92 NC, 93 A2-I/O (io), 94 A3-I/O (io), 95 NC, 96 NC, 97 A15-I/O (io), 98 A4-I/O (io), 99 A14-I/O (io), 100 A5-I/O (io)

## XC3042-50CB100M
designator U?
Logic Cell Array with 144 CLBs, with 64 I/O Pins, 100-Pin CQFP, Military Grade; ComponentAvailability: Not for New Design
footprint CB100_N (CQFP, 100-Leads, Body 19x19mm; Pitch 0.635mm, Gullwing Leadform, IPC Medium Density)
footprint CB100_L (CQFP, 100-Leads, Body 19x19mm; Pitch 0.635mm, Gullwing Leadform, IPC High Density)
footprint CB100_M (CQFP, 100-Leads, Body 19x19mm; Pitch 0.635mm, Gullwing Leadform, IPC Low Density)
3D model XC3042-CB100 (100-Pin Ceramic Brazed Quad Flat Pack (CB100))
pins: 1 GND (power), 2 A13-I/O (io), 3 A6-I/O (io), 4 A12-I/O (io), 5 A7-I/O (io), 6 NC, 7 NC, 8 A11-I/O (io), 9 A8-I/O (io), 10 A10-I/O (io), 11 A9-I/O (io), 12 NC, 13 NC, 14 ~{PWRDWN} (in), 15 TCKLIN-I/O (io), 16 NC, 17 NC, 18 NC, 19 I/O (io), 20 I/O (io), 21 I/O (io), 22 I/O (io), 23 I/O (io), 24 I/O (io), 25 I/O (io), 26 VCC (power), 27 I/O (io), 28 I/O (io), 29 I/O (io), 30 I/O (io), 31 I/O (io), 32 I/O (io), 33 I/O (io), 34 I/O (io), 35 NC, 36 NC, 37 M1~{-RD} (out), 38 NC, 39 M0-RT (in), 40 NC, 41 M2-I/O (io), 42 HDC-I/O (io), 43 I/O (io), 44 ~{LDC}-I/O (io), 45 NC, 46 NC, 47 I/O (io), 48 I/O (io), 49 I/O (io), 50 ~{INIT}-I/O (io), 51 GND (power), 52 I/O (io), 53 I/O (io), 54 I/O (io), 55 I/O (io), 56 I/O (io), 57 I/O (io), 58 I/O (io), 59 NC, 60 NC, 61 XTAL2-I/O (io), 62 NC, 63 ~{RESET} (in), 64 NC, 65 DONE~{-PROG} (out), 66 D7-I/O (io), 67 XTAL1-I/O (io), 68 D6-I/O (io), 69 NC, 70 NC, 71 I/O (io), 72 D5-I/O (io), 73 ~{CS0}-I/O (io), 74 D4-I/O (io), 75 I/O (io), 76 VCC (power), 77 D3-I/O (io), 78 ~{CS1}-I/O (io), 79 D2-I/O (io), 80 I/O (io), 81 NC, 82 NC, 83 D1-I/O (io), 84 ~{RCLK}-~{BUSY}/RDY-I/O (io), 85 DO-DIN-I/O (io), 86 DOUT-I/O (io), 87 CCLK (io), 88 NC, 89 NC, 90 A0~{-WS}-I/O (io), 91 A1-CS2-I/O (io), 92 NC, 93 A2-I/O (io), 94 A3-I/O (io), 95 NC, 96 NC, 97 A15-I/O (io), 98 A4-I/O (io), 99 A14-I/O (io), 100 A5-I/O (io)

## XC3042-50CQ100M
designator U?
Logic Cell Array with 144 CLBs, with 64 I/O Pins, 100-Pin CQFP, Military Grade; ComponentAvailability: Not for New Design
footprint CB100_N (CQFP, 100-Leads, Body 19x19mm; Pitch 0.635mm, Gullwing Leadform, IPC Medium Density)
footprint CB100_L (CQFP, 100-Leads, Body 19x19mm; Pitch 0.635mm, Gullwing Leadform, IPC High Density)
footprint CB100_M (CQFP, 100-Leads, Body 19x19mm; Pitch 0.635mm, Gullwing Leadform, IPC Low Density)
3D model XC3042-CB100 (100-Pin Ceramic Brazed Quad Flat Pack (CB100))
pins: 1 GND (power), 2 A13-I/O (io), 3 A6-I/O (io), 4 A12-I/O (io), 5 A7-I/O (io), 6 NC, 7 NC, 8 A11-I/O (io), 9 A8-I/O (io), 10 A10-I/O (io), 11 A9-I/O (io), 12 NC, 13 NC, 14 ~{PWRDWN} (in), 15 TCKLIN-I/O (io), 16 NC, 17 NC, 18 NC, 19 I/O (io), 20 I/O (io), 21 I/O (io), 22 I/O (io), 23 I/O (io), 24 I/O (io), 25 I/O (io), 26 VCC (power), 27 I/O (io), 28 I/O (io), 29 I/O (io), 30 I/O (io), 31 I/O (io), 32 I/O (io), 33 I/O (io), 34 I/O (io), 35 NC, 36 NC, 37 M1~{-RD} (out), 38 NC, 39 M0-RT (in), 40 NC, 41 M2-I/O (io), 42 HDC-I/O (io), 43 I/O (io), 44 ~{LDC}-I/O (io), 45 NC, 46 NC, 47 I/O (io), 48 I/O (io), 49 I/O (io), 50 ~{INIT}-I/O (io), 51 GND (power), 52 I/O (io), 53 I/O (io), 54 I/O (io), 55 I/O (io), 56 I/O (io), 57 I/O (io), 58 I/O (io), 59 NC, 60 NC, 61 XTAL2-I/O (io), 62 NC, 63 ~{RESET} (in), 64 NC, 65 DONE~{-PROG} (out), 66 D7-I/O (io), 67 XTAL1-I/O (io), 68 D6-I/O (io), 69 NC, 70 NC, 71 I/O (io), 72 D5-I/O (io), 73 ~{CS0}-I/O (io), 74 D4-I/O (io), 75 I/O (io), 76 VCC (power), 77 D3-I/O (io), 78 ~{CS1}-I/O (io), 79 D2-I/O (io), 80 I/O (io), 81 NC, 82 NC, 83 D1-I/O (io), 84 ~{RCLK}-~{BUSY}/RDY-I/O (io), 85 DO-DIN-I/O (io), 86 DOUT-I/O (io), 87 CCLK (io), 88 NC, 89 NC, 90 A0~{-WS}-I/O (io), 91 A1-CS2-I/O (io), 92 NC, 93 A2-I/O (io), 94 A3-I/O (io), 95 NC, 96 NC, 97 A15-I/O (io), 98 A4-I/O (io), 99 A14-I/O (io), 100 A5-I/O (io)

## XC3042-50PG84B
designator U?
Logic Cell Array with 144 CLBs, with 64 I/O Pins, 84-Pin PGA, Military Class B Grade; ComponentAvailability: Not for New Design
footprint PG84 (PGA, 85-Leads, Body 28x28mm, Pitch 2.54mm)
3D model XC3042-PG84 (84-Pin Ceramic Pin Grid Array (PG84))
pins: A1 A9-I/O (io), A2 A8-I/O (io), A3 A11-I/O (io), A4 NC, A5 A6-I/O (io), A6 A13-I/O (io), A7 A14-I/O (io), A8 NC, A9 A3-I/O (io), A10 A2-I/O (io), A11 CCLK (io), B1 NC, B2 ~{PWRDWN} (in), B3 A10-I/O (io), B4 NC, B5 A12-I/O (io), B6 A15-I/O (io), B7 A4-I/O (io), B8 NC, B9 A1-CS2-I/O (io), B10 A0~{-WS}-I/O (io), B11 D0-DIN-I/O (io), C1 I/O (io), C2 TCLKIN-I/O (io), C5 A7-I/O (io), C6 GND (power), C7 A5-I/O (io), C10 DOUT-I/O (io), C11 RDY~{/BUSY}-~{RCLK}-I/O (io), D1 I/O (io), D2 I/O (io), D10 D1-I/O (io), D11 NC, E1 I/O (io), E2 I/O (io), E3 I/O (io), E9 I/O (io), E10 D2-I/O (io), E11 ~{CS}1-I/O (io), F1 I/O (io), F2 I/O (io), F3 VCC (power), F9 VCC (power), F10 D5-I/O (io), F11 D3-I/O (io), G1 I/O (io), G2 I/O (io), G3 I/O (io), G9 I/O (io), G10 ~{CS}0-I/O (io), G11 D4-I/O (io), H1 I/O (io), H2 I/O (io), H10 D6-I/O (io), H11 I/O (io), J1 I/O (io), J2 M1~{-RDATA} (out), J5 I/O (io), J6 GND (power), J7 I/O (io), J10 DONE-~{PROG} (out), J11 XTL1(OUT)-BLKIN-I/O (io), K1 I/O (io), K2 M2-I/O (io), K3 HDC-I/O (io), K4 I/O (io), K5 I/O (io), K6 ~{INIT}-I/O (io), K7 I/O (io), K8 I/O (io), K9 I/O (io), K10 ~{RESET} (in), K11 D7-I/O (io), L1 M0-RTRIG (in), L2 I/O (io), L3 ~{LDC}-I/O (io), L4 NC, L5 NC, L6 I/O (io), L7 I/O (io), L8 I/O (io), L9 NC, L10 NC, L11 XTL2(IN) -I/O (io)

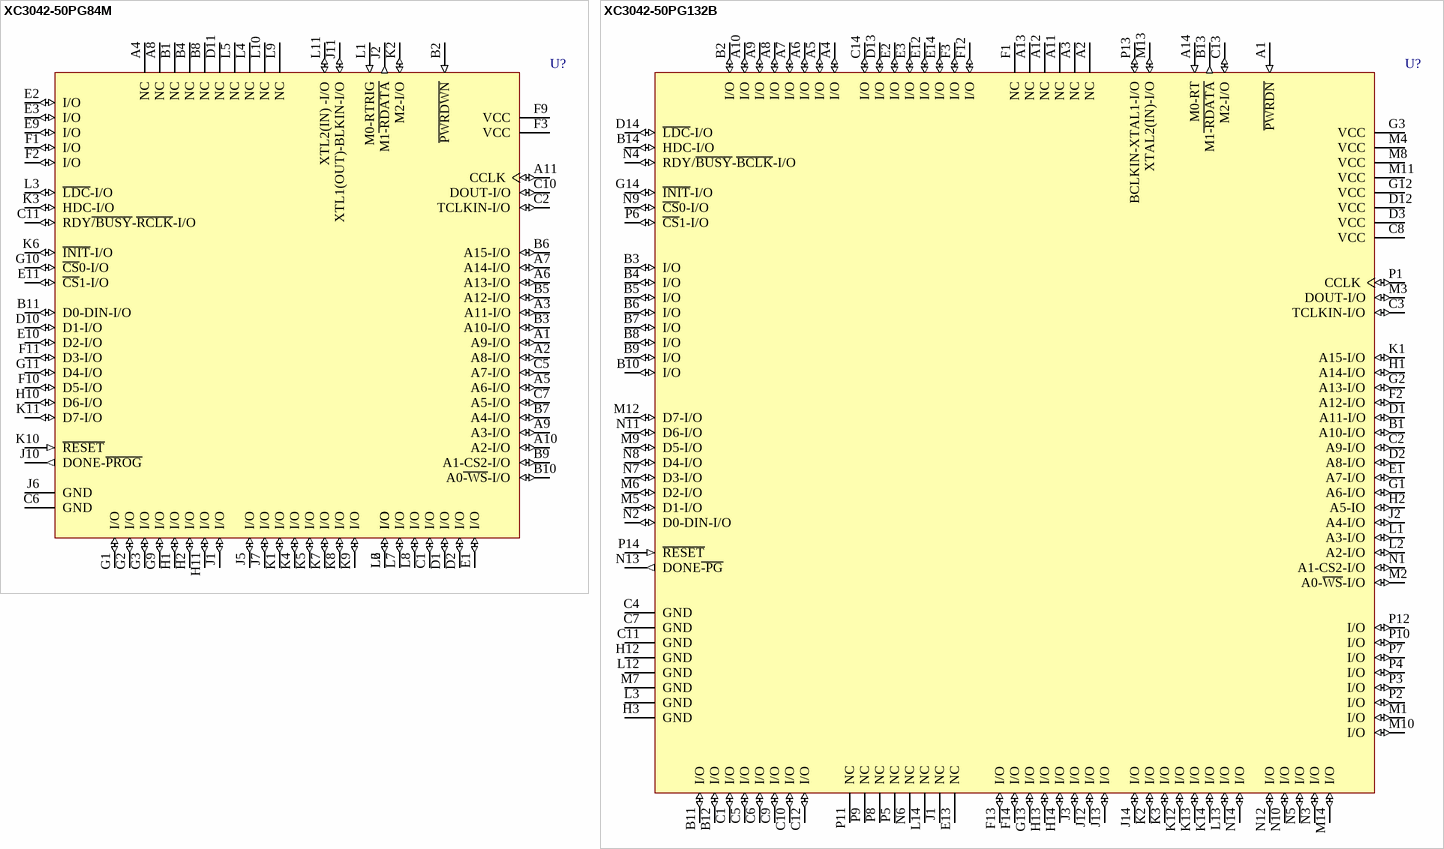
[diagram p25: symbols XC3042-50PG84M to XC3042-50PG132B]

## XC3042-50PG84M
designator U?
Logic Cell Array with 144 CLBs, with 64 I/O Pins, 84-Pin PGA, Military Grade; ComponentAvailability: Not for New Design
footprint PG84 (PGA, 85-Leads, Body 28x28mm, Pitch 2.54mm)
3D model XC3042-PG84 (84-Pin Ceramic Pin Grid Array (PG84))
pins: A1 A9-I/O (io), A2 A8-I/O (io), A3 A11-I/O (io), A4 NC, A5 A6-I/O (io), A6 A13-I/O (io), A7 A14-I/O (io), A8 NC, A9 A3-I/O (io), A10 A2-I/O (io), A11 CCLK (io), B1 NC, B2 ~{PWRDWN} (in), B3 A10-I/O (io), B4 NC, B5 A12-I/O (io), B6 A15-I/O (io), B7 A4-I/O (io), B8 NC, B9 A1-CS2-I/O (io), B10 A0~{-WS}-I/O (io), B11 D0-DIN-I/O (io), C1 I/O (io), C2 TCLKIN-I/O (io), C5 A7-I/O (io), C6 GND (power), C7 A5-I/O (io), C10 DOUT-I/O (io), C11 RDY~{/BUSY}-~{RCLK}-I/O (io), D1 I/O (io), D2 I/O (io), D10 D1-I/O (io), D11 NC, E1 I/O (io), E2 I/O (io), E3 I/O (io), E9 I/O (io), E10 D2-I/O (io), E11 ~{CS}1-I/O (io), F1 I/O (io), F2 I/O (io), F3 VCC (power), F9 VCC (power), F10 D5-I/O (io), F11 D3-I/O (io), G1 I/O (io), G2 I/O (io), G3 I/O (io), G9 I/O (io), G10 ~{CS}0-I/O (io), G11 D4-I/O (io), H1 I/O (io), H2 I/O (io), H10 D6-I/O (io), H11 I/O (io), J1 I/O (io), J2 M1~{-RDATA} (out), J5 I/O (io), J6 GND (power), J7 I/O (io), J10 DONE-~{PROG} (out), J11 XTL1(OUT)-BLKIN-I/O (io), K1 I/O (io), K2 M2-I/O (io), K3 HDC-I/O (io), K4 I/O (io), K5 I/O (io), K6 ~{INIT}-I/O (io), K7 I/O (io), K8 I/O (io), K9 I/O (io), K10 ~{RESET} (in), K11 D7-I/O (io), L1 M0-RTRIG (in), L2 I/O (io), L3 ~{LDC}-I/O (io), L4 NC, L5 NC, L6 I/O (io), L7 I/O (io), L8 I/O (io), L9 NC, L10 NC, L11 XTL2(IN) -I/O (io)

## XC3042-50PG132B
designator U?
Logic Cell Array with 144 CLBs, with 96 I/O Pins, 132-Pin PGA, Military Class B Grade; ComponentAvailability: Not for New Design
footprint PG132 (PGA, 132-Leads, Body 37x37mm, Pitch 2.54mm)
3D model XC3042-PG132 (132-Pin Ceramic Pin Grid Array (PG132))
pins: A1 ~{PWRDN} (in), A2 NC, A3 NC, A4 I/O (io), A5 I/O (io), A6 I/O (io), A7 I/O (io), A8 I/O (io), A9 I/O (io), A10 I/O (io), A11 NC, A12 NC, A13 NC, A14 M0-RT (in), B1 A10-I/O (io), B2 I/O (io), B3 I/O (io), B4 I/O (io), B5 I/O (io), B6 I/O (io), B7 I/O (io), B8 I/O (io), B9 I/O (io), B10 I/O (io), B11 I/O (io), B12 I/O (io), B13 M1~{-RDATA} (out), B14 HDC-I/O (io), C1 I/O (io), C2 A9-I/O (io), C3 TCLKIN-I/O (io), C4 GND (power), C5 I/O (io), C6 I/O (io), C7 GND (power), C8 VCC (power), C9 I/O (io), C10 I/O (io), C11 GND (power), C12 I/O (io), C13 M2-I/O (io), C14 I/O (io), D1 A11-I/O (io), D2 A8-I/O (io), D3 VCC (power), D12 VCC (power), D13 I/O (io), D14 ~{LDC}-I/O (io), E1 A7-I/O (io), E2 I/O (io), E3 I/O (io), E12 I/O (io), E13 NC, E14 I/O (io), F1 NC, F2 A12-I/O (io), F3 I/O (io), F12 I/O (io), F13 I/O (io), F14 I/O (io), G1 A6-I/O (io), G2 A13-I/O (io), G3 VCC (power), G12 VCC (power), G13 I/O (io), G14 ~{INIT}-I/O (io), H1 A14-I/O (io), H2 A5-IO (io), H3 GND (power), H12 GND (power), H13 I/O (io), H14 I/O (io), J1 NC, J2 A4-I/O (io), J3 I/O (io), J12 I/O (io), J13 I/O (io), J14 I/O (io), K1 A15-I/O (io), K2 I/O (io), K3 I/O (io), K12 I/O (io), K13 I/O (io), K14 I/O (io), L1 A3-I/O (io), L2 A2-I/O (io), L3 GND (power), L12 GND (power), L13 I/O (io), L14 NC, M1 I/O (io), M2 A0-~{WS}-I/O (io), M3 DOUT-I/O (io), M4 VCC (power), M5 D1-I/O (io), M6 D2-I/O (io), M7 GND (power), M8 VCC (power), M9 D5-I/O (io), M10 I/O (io), M11 VCC (power), M12 D7-I/O (io), M13 XTAL2(IN)-I/O (io), M14 I/O (io), N1 A1-CS2-I/O (io), N2 D0-DIN-I/O (io), N3 I/O (io), N4 RDY/~{BUSY}-~{BCLK}-I/O (io), N5 I/O (io), N6 NC, N7 D3-I/O (io), N8 D4-I/O (io), N9 ~{CS}0-I/O (io), N10 I/O (io), N11 D6-I/O (io), N12 I/O (io), N13 DONE~{-PG} (out), N14 I/O (io), P1 CCLK (io), P2 I/O (io), P3 I/O (io), P4 I/O (io), P5 NC, P6 ~{CS}1-I/O (io), P7 I/O (io), P8 NC, P9 NC, P10 I/O (io), P11 NC, P12 I/O (io), P13 BCLKIN-XTAL1-I/O (io), P14 ~{RESET} (in)

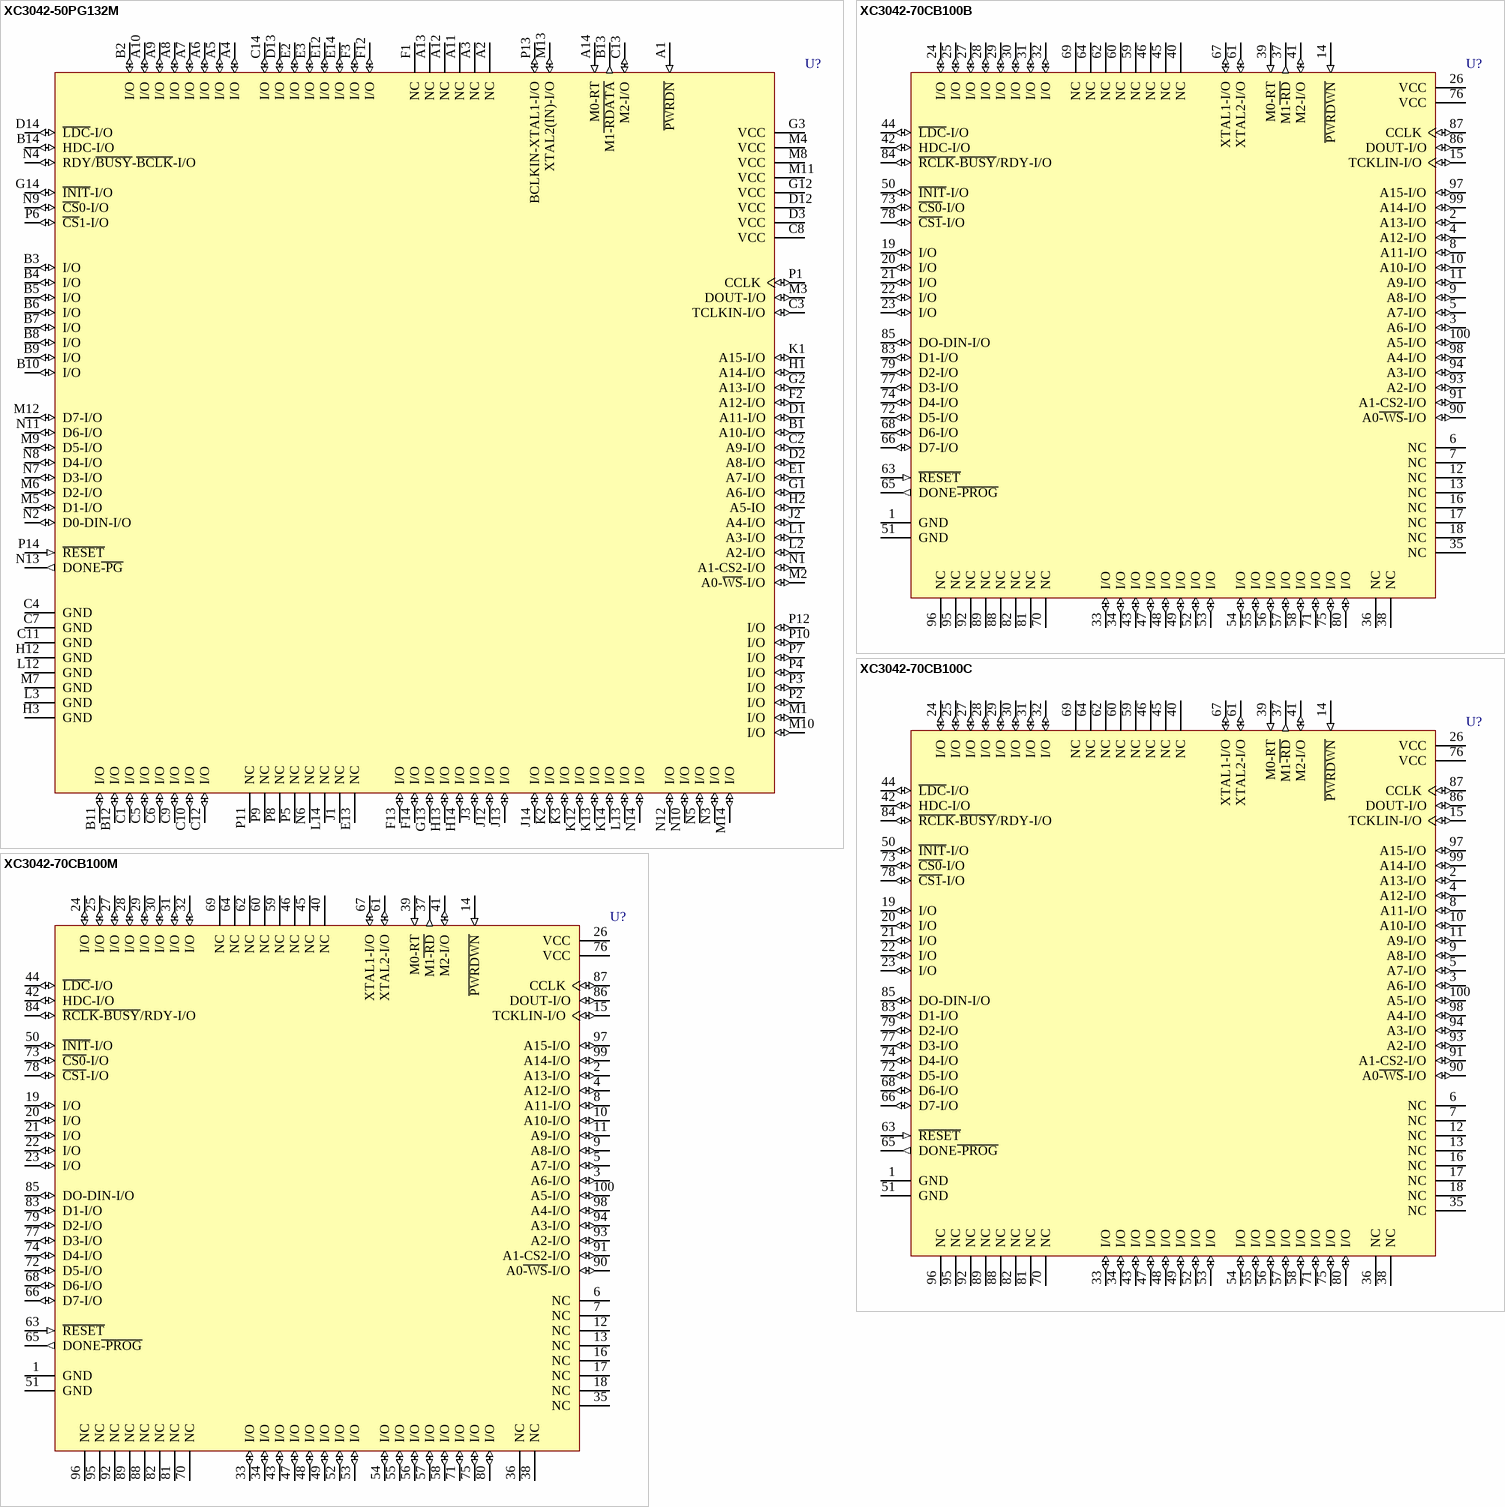
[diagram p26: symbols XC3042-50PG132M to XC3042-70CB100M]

## XC3042-50PG132M
designator U?
Logic Cell Array with 144 CLBs, with 96 I/O Pins, 132-Pin PGA, Military Grade; ComponentAvailability: Not for New Design
footprint PG132 (PGA, 132-Leads, Body 37x37mm, Pitch 2.54mm)
3D model XC3042-PG132 (132-Pin Ceramic Pin Grid Array (PG132))
pins: A1 ~{PWRDN} (in), A2 NC, A3 NC, A4 I/O (io), A5 I/O (io), A6 I/O (io), A7 I/O (io), A8 I/O (io), A9 I/O (io), A10 I/O (io), A11 NC, A12 NC, A13 NC, A14 M0-RT (in), B1 A10-I/O (io), B2 I/O (io), B3 I/O (io), B4 I/O (io), B5 I/O (io), B6 I/O (io), B7 I/O (io), B8 I/O (io), B9 I/O (io), B10 I/O (io), B11 I/O (io), B12 I/O (io), B13 M1~{-RDATA} (out), B14 HDC-I/O (io), C1 I/O (io), C2 A9-I/O (io), C3 TCLKIN-I/O (io), C4 GND (power), C5 I/O (io), C6 I/O (io), C7 GND (power), C8 VCC (power), C9 I/O (io), C10 I/O (io), C11 GND (power), C12 I/O (io), C13 M2-I/O (io), C14 I/O (io), D1 A11-I/O (io), D2 A8-I/O (io), D3 VCC (power), D12 VCC (power), D13 I/O (io), D14 ~{LDC}-I/O (io), E1 A7-I/O (io), E2 I/O (io), E3 I/O (io), E12 I/O (io), E13 NC, E14 I/O (io), F1 NC, F2 A12-I/O (io), F3 I/O (io), F12 I/O (io), F13 I/O (io), F14 I/O (io), G1 A6-I/O (io), G2 A13-I/O (io), G3 VCC (power), G12 VCC (power), G13 I/O (io), G14 ~{INIT}-I/O (io), H1 A14-I/O (io), H2 A5-IO (io), H3 GND (power), H12 GND (power), H13 I/O (io), H14 I/O (io), J1 NC, J2 A4-I/O (io), J3 I/O (io), J12 I/O (io), J13 I/O (io), J14 I/O (io), K1 A15-I/O (io), K2 I/O (io), K3 I/O (io), K12 I/O (io), K13 I/O (io), K14 I/O (io), L1 A3-I/O (io), L2 A2-I/O (io), L3 GND (power), L12 GND (power), L13 I/O (io), L14 NC, M1 I/O (io), M2 A0-~{WS}-I/O (io), M3 DOUT-I/O (io), M4 VCC (power), M5 D1-I/O (io), M6 D2-I/O (io), M7 GND (power), M8 VCC (power), M9 D5-I/O (io), M10 I/O (io), M11 VCC (power), M12 D7-I/O (io), M13 XTAL2(IN)-I/O (io), M14 I/O (io), N1 A1-CS2-I/O (io), N2 D0-DIN-I/O (io), N3 I/O (io), N4 RDY/~{BUSY}-~{BCLK}-I/O (io), N5 I/O (io), N6 NC, N7 D3-I/O (io), N8 D4-I/O (io), N9 ~{CS}0-I/O (io), N10 I/O (io), N11 D6-I/O (io), N12 I/O (io), N13 DONE~{-PG} (out), N14 I/O (io), P1 CCLK (io), P2 I/O (io), P3 I/O (io), P4 I/O (io), P5 NC, P6 ~{CS}1-I/O (io), P7 I/O (io), P8 NC, P9 NC, P10 I/O (io), P11 NC, P12 I/O (io), P13 BCLKIN-XTAL1-I/O (io), P14 ~{RESET} (in)

## XC3042-70CB100B
designator U?
Logic Cell Array with 144 CLBs, with 64 I/O Pins, 100-Pin CQFP, Military Class B Grade; ComponentAvailability: Not for New Design
footprint CB100_N (CQFP, 100-Leads, Body 19x19mm; Pitch 0.635mm, Gullwing Leadform, IPC Medium Density)
footprint CB100_L (CQFP, 100-Leads, Body 19x19mm; Pitch 0.635mm, Gullwing Leadform, IPC High Density)
footprint CB100_M (CQFP, 100-Leads, Body 19x19mm; Pitch 0.635mm, Gullwing Leadform, IPC Low Density)
3D model XC3042-CB100 (100-Pin Ceramic Brazed Quad Flat Pack (CB100))
pins: 1 GND (power), 2 A13-I/O (io), 3 A6-I/O (io), 4 A12-I/O (io), 5 A7-I/O (io), 6 NC, 7 NC, 8 A11-I/O (io), 9 A8-I/O (io), 10 A10-I/O (io), 11 A9-I/O (io), 12 NC, 13 NC, 14 ~{PWRDWN} (in), 15 TCKLIN-I/O (io), 16 NC, 17 NC, 18 NC, 19 I/O (io), 20 I/O (io), 21 I/O (io), 22 I/O (io), 23 I/O (io), 24 I/O (io), 25 I/O (io), 26 VCC (power), 27 I/O (io), 28 I/O (io), 29 I/O (io), 30 I/O (io), 31 I/O (io), 32 I/O (io), 33 I/O (io), 34 I/O (io), 35 NC, 36 NC, 37 M1~{-RD} (out), 38 NC, 39 M0-RT (in), 40 NC, 41 M2-I/O (io), 42 HDC-I/O (io), 43 I/O (io), 44 ~{LDC}-I/O (io), 45 NC, 46 NC, 47 I/O (io), 48 I/O (io), 49 I/O (io), 50 ~{INIT}-I/O (io), 51 GND (power), 52 I/O (io), 53 I/O (io), 54 I/O (io), 55 I/O (io), 56 I/O (io), 57 I/O (io), 58 I/O (io), 59 NC, 60 NC, 61 XTAL2-I/O (io), 62 NC, 63 ~{RESET} (in), 64 NC, 65 DONE~{-PROG} (out), 66 D7-I/O (io), 67 XTAL1-I/O (io), 68 D6-I/O (io), 69 NC, 70 NC, 71 I/O (io), 72 D5-I/O (io), 73 ~{CS0}-I/O (io), 74 D4-I/O (io), 75 I/O (io), 76 VCC (power), 77 D3-I/O (io), 78 ~{CS1}-I/O (io), 79 D2-I/O (io), 80 I/O (io), 81 NC, 82 NC, 83 D1-I/O (io), 84 ~{RCLK}-~{BUSY}/RDY-I/O (io), 85 DO-DIN-I/O (io), 86 DOUT-I/O (io), 87 CCLK (io), 88 NC, 89 NC, 90 A0~{-WS}-I/O (io), 91 A1-CS2-I/O (io), 92 NC, 93 A2-I/O (io), 94 A3-I/O (io), 95 NC, 96 NC, 97 A15-I/O (io), 98 A4-I/O (io), 99 A14-I/O (io), 100 A5-I/O (io)

## XC3042-70CB100C
designator U?
Logic Cell Array with 144 CLBs, with 64 I/O Pins, 100-Pin CQFP, Commercial Grade; ComponentAvailability: Not for New Design
footprint CB100_N (CQFP, 100-Leads, Body 19x19mm; Pitch 0.635mm, Gullwing Leadform, IPC Medium Density)
footprint CB100_L (CQFP, 100-Leads, Body 19x19mm; Pitch 0.635mm, Gullwing Leadform, IPC High Density)
footprint CB100_M (CQFP, 100-Leads, Body 19x19mm; Pitch 0.635mm, Gullwing Leadform, IPC Low Density)
3D model XC3042-CB100 (100-Pin Ceramic Brazed Quad Flat Pack (CB100))
pins: 1 GND (power), 2 A13-I/O (io), 3 A6-I/O (io), 4 A12-I/O (io), 5 A7-I/O (io), 6 NC, 7 NC, 8 A11-I/O (io), 9 A8-I/O (io), 10 A10-I/O (io), 11 A9-I/O (io), 12 NC, 13 NC, 14 ~{PWRDWN} (in), 15 TCKLIN-I/O (io), 16 NC, 17 NC, 18 NC, 19 I/O (io), 20 I/O (io), 21 I/O (io), 22 I/O (io), 23 I/O (io), 24 I/O (io), 25 I/O (io), 26 VCC (power), 27 I/O (io), 28 I/O (io), 29 I/O (io), 30 I/O (io), 31 I/O (io), 32 I/O (io), 33 I/O (io), 34 I/O (io), 35 NC, 36 NC, 37 M1~{-RD} (out), 38 NC, 39 M0-RT (in), 40 NC, 41 M2-I/O (io), 42 HDC-I/O (io), 43 I/O (io), 44 ~{LDC}-I/O (io), 45 NC, 46 NC, 47 I/O (io), 48 I/O (io), 49 I/O (io), 50 ~{INIT}-I/O (io), 51 GND (power), 52 I/O (io), 53 I/O (io), 54 I/O (io), 55 I/O (io), 56 I/O (io), 57 I/O (io), 58 I/O (io), 59 NC, 60 NC, 61 XTAL2-I/O (io), 62 NC, 63 ~{RESET} (in), 64 NC, 65 DONE~{-PROG} (out), 66 D7-I/O (io), 67 XTAL1-I/O (io), 68 D6-I/O (io), 69 NC, 70 NC, 71 I/O (io), 72 D5-I/O (io), 73 ~{CS0}-I/O (io), 74 D4-I/O (io), 75 I/O (io), 76 VCC (power), 77 D3-I/O (io), 78 ~{CS1}-I/O (io), 79 D2-I/O (io), 80 I/O (io), 81 NC, 82 NC, 83 D1-I/O (io), 84 ~{RCLK}-~{BUSY}/RDY-I/O (io), 85 DO-DIN-I/O (io), 86 DOUT-I/O (io), 87 CCLK (io), 88 NC, 89 NC, 90 A0~{-WS}-I/O (io), 91 A1-CS2-I/O (io), 92 NC, 93 A2-I/O (io), 94 A3-I/O (io), 95 NC, 96 NC, 97 A15-I/O (io), 98 A4-I/O (io), 99 A14-I/O (io), 100 A5-I/O (io)

## XC3042-70CB100M
designator U?
Logic Cell Array with 144 CLBs, with 64 I/O Pins, 100-Pin CQFP, Military Grade; ComponentAvailability: Not for New Design
footprint CB100_N (CQFP, 100-Leads, Body 19x19mm; Pitch 0.635mm, Gullwing Leadform, IPC Medium Density)
footprint CB100_L (CQFP, 100-Leads, Body 19x19mm; Pitch 0.635mm, Gullwing Leadform, IPC High Density)
footprint CB100_M (CQFP, 100-Leads, Body 19x19mm; Pitch 0.635mm, Gullwing Leadform, IPC Low Density)
3D model XC3042-CB100 (100-Pin Ceramic Brazed Quad Flat Pack (CB100))
pins: 1 GND (power), 2 A13-I/O (io), 3 A6-I/O (io), 4 A12-I/O (io), 5 A7-I/O (io), 6 NC, 7 NC, 8 A11-I/O (io), 9 A8-I/O (io), 10 A10-I/O (io), 11 A9-I/O (io), 12 NC, 13 NC, 14 ~{PWRDWN} (in), 15 TCKLIN-I/O (io), 16 NC, 17 NC, 18 NC, 19 I/O (io), 20 I/O (io), 21 I/O (io), 22 I/O (io), 23 I/O (io), 24 I/O (io), 25 I/O (io), 26 VCC (power), 27 I/O (io), 28 I/O (io), 29 I/O (io), 30 I/O (io), 31 I/O (io), 32 I/O (io), 33 I/O (io), 34 I/O (io), 35 NC, 36 NC, 37 M1~{-RD} (out), 38 NC, 39 M0-RT (in), 40 NC, 41 M2-I/O (io), 42 HDC-I/O (io), 43 I/O (io), 44 ~{LDC}-I/O (io), 45 NC, 46 NC, 47 I/O (io), 48 I/O (io), 49 I/O (io), 50 ~{INIT}-I/O (io), 51 GND (power), 52 I/O (io), 53 I/O (io), 54 I/O (io), 55 I/O (io), 56 I/O (io), 57 I/O (io), 58 I/O (io), 59 NC, 60 NC, 61 XTAL2-I/O (io), 62 NC, 63 ~{RESET} (in), 64 NC, 65 DONE~{-PROG} (out), 66 D7-I/O (io), 67 XTAL1-I/O (io), 68 D6-I/O (io), 69 NC, 70 NC, 71 I/O (io), 72 D5-I/O (io), 73 ~{CS0}-I/O (io), 74 D4-I/O (io), 75 I/O (io), 76 VCC (power), 77 D3-I/O (io), 78 ~{CS1}-I/O (io), 79 D2-I/O (io), 80 I/O (io), 81 NC, 82 NC, 83 D1-I/O (io), 84 ~{RCLK}-~{BUSY}/RDY-I/O (io), 85 DO-DIN-I/O (io), 86 DOUT-I/O (io), 87 CCLK (io), 88 NC, 89 NC, 90 A0~{-WS}-I/O (io), 91 A1-CS2-I/O (io), 92 NC, 93 A2-I/O (io), 94 A3-I/O (io), 95 NC, 96 NC, 97 A15-I/O (io), 98 A4-I/O (io), 99 A14-I/O (io), 100 A5-I/O (io)

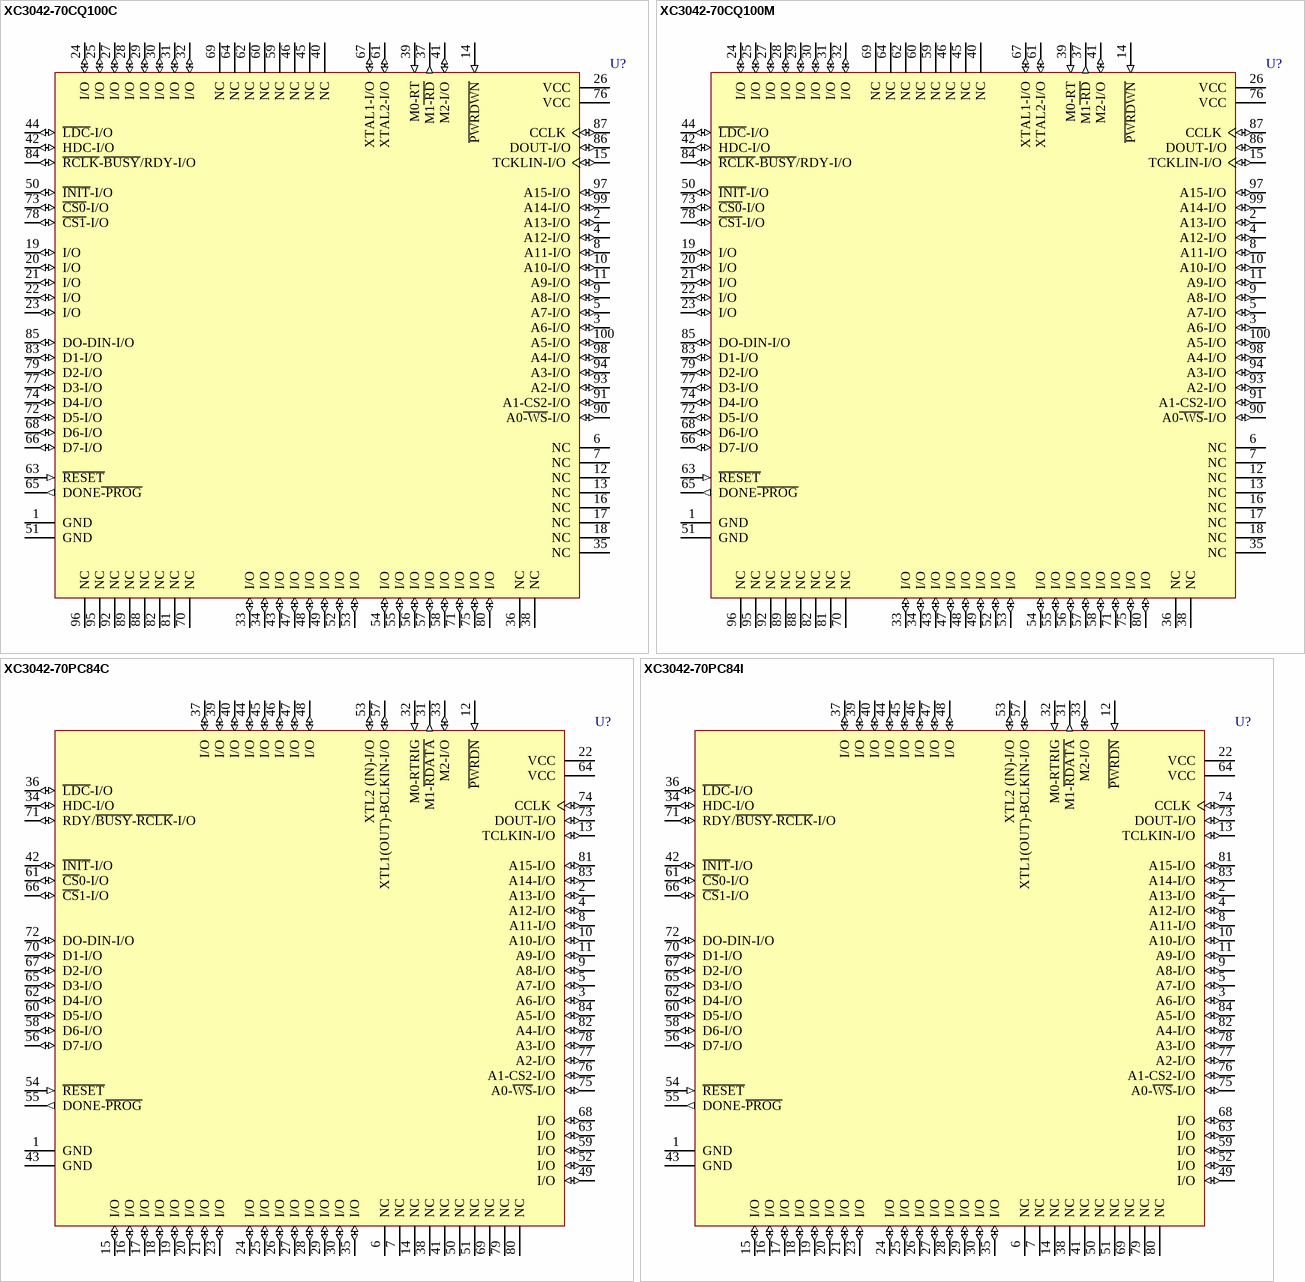
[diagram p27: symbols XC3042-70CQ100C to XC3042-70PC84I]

## XC3042-70CQ100C
designator U?
Logic Cell Array with 144 CLBs, with 64 I/O Pins, 100-Pin CQFP, Commercial Grade; ComponentAvailability: Not for New Design
footprint CB100_N (CQFP, 100-Leads, Body 19x19mm; Pitch 0.635mm, Gullwing Leadform, IPC Medium Density)
footprint CB100_L (CQFP, 100-Leads, Body 19x19mm; Pitch 0.635mm, Gullwing Leadform, IPC High Density)
footprint CB100_M (CQFP, 100-Leads, Body 19x19mm; Pitch 0.635mm, Gullwing Leadform, IPC Low Density)
3D model XC3042-CB100 (100-Pin Ceramic Brazed Quad Flat Pack (CB100))
pins: 1 GND (power), 2 A13-I/O (io), 3 A6-I/O (io), 4 A12-I/O (io), 5 A7-I/O (io), 6 NC, 7 NC, 8 A11-I/O (io), 9 A8-I/O (io), 10 A10-I/O (io), 11 A9-I/O (io), 12 NC, 13 NC, 14 ~{PWRDWN} (in), 15 TCKLIN-I/O (io), 16 NC, 17 NC, 18 NC, 19 I/O (io), 20 I/O (io), 21 I/O (io), 22 I/O (io), 23 I/O (io), 24 I/O (io), 25 I/O (io), 26 VCC (power), 27 I/O (io), 28 I/O (io), 29 I/O (io), 30 I/O (io), 31 I/O (io), 32 I/O (io), 33 I/O (io), 34 I/O (io), 35 NC, 36 NC, 37 M1~{-RD} (out), 38 NC, 39 M0-RT (in), 40 NC, 41 M2-I/O (io), 42 HDC-I/O (io), 43 I/O (io), 44 ~{LDC}-I/O (io), 45 NC, 46 NC, 47 I/O (io), 48 I/O (io), 49 I/O (io), 50 ~{INIT}-I/O (io), 51 GND (power), 52 I/O (io), 53 I/O (io), 54 I/O (io), 55 I/O (io), 56 I/O (io), 57 I/O (io), 58 I/O (io), 59 NC, 60 NC, 61 XTAL2-I/O (io), 62 NC, 63 ~{RESET} (in), 64 NC, 65 DONE~{-PROG} (out), 66 D7-I/O (io), 67 XTAL1-I/O (io), 68 D6-I/O (io), 69 NC, 70 NC, 71 I/O (io), 72 D5-I/O (io), 73 ~{CS0}-I/O (io), 74 D4-I/O (io), 75 I/O (io), 76 VCC (power), 77 D3-I/O (io), 78 ~{CS1}-I/O (io), 79 D2-I/O (io), 80 I/O (io), 81 NC, 82 NC, 83 D1-I/O (io), 84 ~{RCLK}-~{BUSY}/RDY-I/O (io), 85 DO-DIN-I/O (io), 86 DOUT-I/O (io), 87 CCLK (io), 88 NC, 89 NC, 90 A0~{-WS}-I/O (io), 91 A1-CS2-I/O (io), 92 NC, 93 A2-I/O (io), 94 A3-I/O (io), 95 NC, 96 NC, 97 A15-I/O (io), 98 A4-I/O (io), 99 A14-I/O (io), 100 A5-I/O (io)

## XC3042-70CQ100M
designator U?
Logic Cell Array with 144 CLBs, with 64 I/O Pins, 100-Pin CQFP, Military Grade; ComponentAvailability: Not for New Design
footprint CB100_N (CQFP, 100-Leads, Body 19x19mm; Pitch 0.635mm, Gullwing Leadform, IPC Medium Density)
footprint CB100_L (CQFP, 100-Leads, Body 19x19mm; Pitch 0.635mm, Gullwing Leadform, IPC High Density)
footprint CB100_M (CQFP, 100-Leads, Body 19x19mm; Pitch 0.635mm, Gullwing Leadform, IPC Low Density)
3D model XC3042-CB100 (100-Pin Ceramic Brazed Quad Flat Pack (CB100))
pins: 1 GND (power), 2 A13-I/O (io), 3 A6-I/O (io), 4 A12-I/O (io), 5 A7-I/O (io), 6 NC, 7 NC, 8 A11-I/O (io), 9 A8-I/O (io), 10 A10-I/O (io), 11 A9-I/O (io), 12 NC, 13 NC, 14 ~{PWRDWN} (in), 15 TCKLIN-I/O (io), 16 NC, 17 NC, 18 NC, 19 I/O (io), 20 I/O (io), 21 I/O (io), 22 I/O (io), 23 I/O (io), 24 I/O (io), 25 I/O (io), 26 VCC (power), 27 I/O (io), 28 I/O (io), 29 I/O (io), 30 I/O (io), 31 I/O (io), 32 I/O (io), 33 I/O (io), 34 I/O (io), 35 NC, 36 NC, 37 M1~{-RD} (out), 38 NC, 39 M0-RT (in), 40 NC, 41 M2-I/O (io), 42 HDC-I/O (io), 43 I/O (io), 44 ~{LDC}-I/O (io), 45 NC, 46 NC, 47 I/O (io), 48 I/O (io), 49 I/O (io), 50 ~{INIT}-I/O (io), 51 GND (power), 52 I/O (io), 53 I/O (io), 54 I/O (io), 55 I/O (io), 56 I/O (io), 57 I/O (io), 58 I/O (io), 59 NC, 60 NC, 61 XTAL2-I/O (io), 62 NC, 63 ~{RESET} (in), 64 NC, 65 DONE~{-PROG} (out), 66 D7-I/O (io), 67 XTAL1-I/O (io), 68 D6-I/O (io), 69 NC, 70 NC, 71 I/O (io), 72 D5-I/O (io), 73 ~{CS0}-I/O (io), 74 D4-I/O (io), 75 I/O (io), 76 VCC (power), 77 D3-I/O (io), 78 ~{CS1}-I/O (io), 79 D2-I/O (io), 80 I/O (io), 81 NC, 82 NC, 83 D1-I/O (io), 84 ~{RCLK}-~{BUSY}/RDY-I/O (io), 85 DO-DIN-I/O (io), 86 DOUT-I/O (io), 87 CCLK (io), 88 NC, 89 NC, 90 A0~{-WS}-I/O (io), 91 A1-CS2-I/O (io), 92 NC, 93 A2-I/O (io), 94 A3-I/O (io), 95 NC, 96 NC, 97 A15-I/O (io), 98 A4-I/O (io), 99 A14-I/O (io), 100 A5-I/O (io)

## XC3042-70PC84C
designator U?
Logic Cell Array with 144 CLBs, with 64 I/O Pins, 84-Pin PLCC, Commercial Grade; ComponentAvailability: Not for New Design
footprint PC84_N (Leaded Chip Carrier, 84-Leads, Body 29.3x29.3mm, Pitch 1.27mm, IPC Medium Density)
footprint PC84_L (Leaded Chip Carrier, 84-Leads, Body 29.3x29.3mm, Pitch 1.27mm, IPC High Density)
footprint PC84_M (Leaded Chip Carrier, 84-Leads, Body 29.3x29.3mm, Pitch 1.27mm, IPC Low Density)
3D model XC3042-PC84 (84-Pin Plastic Leaded Chip Carrier (PC84))
pins: 1 GND (power), 2 A13-I/O (io), 3 A6-I/O (io), 4 A12-I/O (io), 5 A7-I/O (io), 6 NC, 7 NC, 8 A11-I/O (io), 9 A8-I/O (io), 10 A10-I/O (io), 11 A9-I/O (io), 12 ~{PWRDN} (in), 13 TCLKIN-I/O (io), 14 NC, 15 I/O (io), 16 I/O (io), 17 I/O (io), 18 I/O (io), 19 I/O (io), 20 I/O (io), 21 I/O (io), 22 VCC (power), 23 I/O (io), 24 I/O (io), 25 I/O (io), 26 I/O (io), 27 I/O (io), 28 I/O (io), 29 I/O (io), 30 I/O (io), 31 M1-~{RDATA} (out), 32 M0-RTRIG (in), 33 M2-I/O (io), 34 HDC-I/O (io), 35 I/O (io), 36 ~{LDC}-I/O (io), 37 I/O (io), 38 NC, 39 I/O (io), 40 I/O (io), 41 NC, 42 ~{INIT}-I/O (io), 43 GND (power), 44 I/O (io), 45 I/O (io), 46 I/O (io), 47 I/O (io), 48 I/O (io), 49 I/O (io), 50 NC, 51 NC, 52 I/O (io), 53 XTL2 (IN)-I/O (io), 54 ~{RESET} (in), 55 DONE-~{PROG} (out), 56 D7-I/O (io), 57 XTL1(OUT)-BCLKIN-I/O (io), 58 D6-I/O (io), 59 I/O (io), 60 D5-I/O (io), 61 ~{CS}0-I/O (io), 62 D4-I/O (io), 63 I/O (io), 64 VCC (power), 65 D3-I/O (io), 66 ~{CS}1-I/O (io), 67 D2-I/O (io), 68 I/O (io), 69 NC, 70 D1-I/O (io), 71 RDY/~{BUSY}-~{RCLK}-I/O (io), 72 DO-DIN-I/O (io), 73 DOUT-I/O (io), 74 CCLK (io), 75 A0-~{WS}-I/O (io), 76 A1-CS2-I/O (io), 77 A2-I/O (io), 78 A3-I/O (io), 79 NC, 80 NC, 81 A15-I/O (io), 82 A4-I/O (io), 83 A14-I/O (io), 84 A5-I/O (io)

## XC3042-70PC84I
designator U?
Logic Cell Array with 144 CLBs, with 64 I/O Pins, 84-Pin PLCC, Industrial Grade; ComponentAvailability: Not for New Design
footprint PC84_N (Leaded Chip Carrier, 84-Leads, Body 29.3x29.3mm, Pitch 1.27mm, IPC Medium Density)
footprint PC84_L (Leaded Chip Carrier, 84-Leads, Body 29.3x29.3mm, Pitch 1.27mm, IPC High Density)
footprint PC84_M (Leaded Chip Carrier, 84-Leads, Body 29.3x29.3mm, Pitch 1.27mm, IPC Low Density)
3D model XC3042-PC84 (84-Pin Plastic Leaded Chip Carrier (PC84))
pins: 1 GND (power), 2 A13-I/O (io), 3 A6-I/O (io), 4 A12-I/O (io), 5 A7-I/O (io), 6 NC, 7 NC, 8 A11-I/O (io), 9 A8-I/O (io), 10 A10-I/O (io), 11 A9-I/O (io), 12 ~{PWRDN} (in), 13 TCLKIN-I/O (io), 14 NC, 15 I/O (io), 16 I/O (io), 17 I/O (io), 18 I/O (io), 19 I/O (io), 20 I/O (io), 21 I/O (io), 22 VCC (power), 23 I/O (io), 24 I/O (io), 25 I/O (io), 26 I/O (io), 27 I/O (io), 28 I/O (io), 29 I/O (io), 30 I/O (io), 31 M1-~{RDATA} (out), 32 M0-RTRIG (in), 33 M2-I/O (io), 34 HDC-I/O (io), 35 I/O (io), 36 ~{LDC}-I/O (io), 37 I/O (io), 38 NC, 39 I/O (io), 40 I/O (io), 41 NC, 42 ~{INIT}-I/O (io), 43 GND (power), 44 I/O (io), 45 I/O (io), 46 I/O (io), 47 I/O (io), 48 I/O (io), 49 I/O (io), 50 NC, 51 NC, 52 I/O (io), 53 XTL2 (IN)-I/O (io), 54 ~{RESET} (in), 55 DONE-~{PROG} (out), 56 D7-I/O (io), 57 XTL1(OUT)-BCLKIN-I/O (io), 58 D6-I/O (io), 59 I/O (io), 60 D5-I/O (io), 61 ~{CS}0-I/O (io), 62 D4-I/O (io), 63 I/O (io), 64 VCC (power), 65 D3-I/O (io), 66 ~{CS}1-I/O (io), 67 D2-I/O (io), 68 I/O (io), 69 NC, 70 D1-I/O (io), 71 RDY/~{BUSY}-~{RCLK}-I/O (io), 72 DO-DIN-I/O (io), 73 DOUT-I/O (io), 74 CCLK (io), 75 A0-~{WS}-I/O (io), 76 A1-CS2-I/O (io), 77 A2-I/O (io), 78 A3-I/O (io), 79 NC, 80 NC, 81 A15-I/O (io), 82 A4-I/O (io), 83 A14-I/O (io), 84 A5-I/O (io)

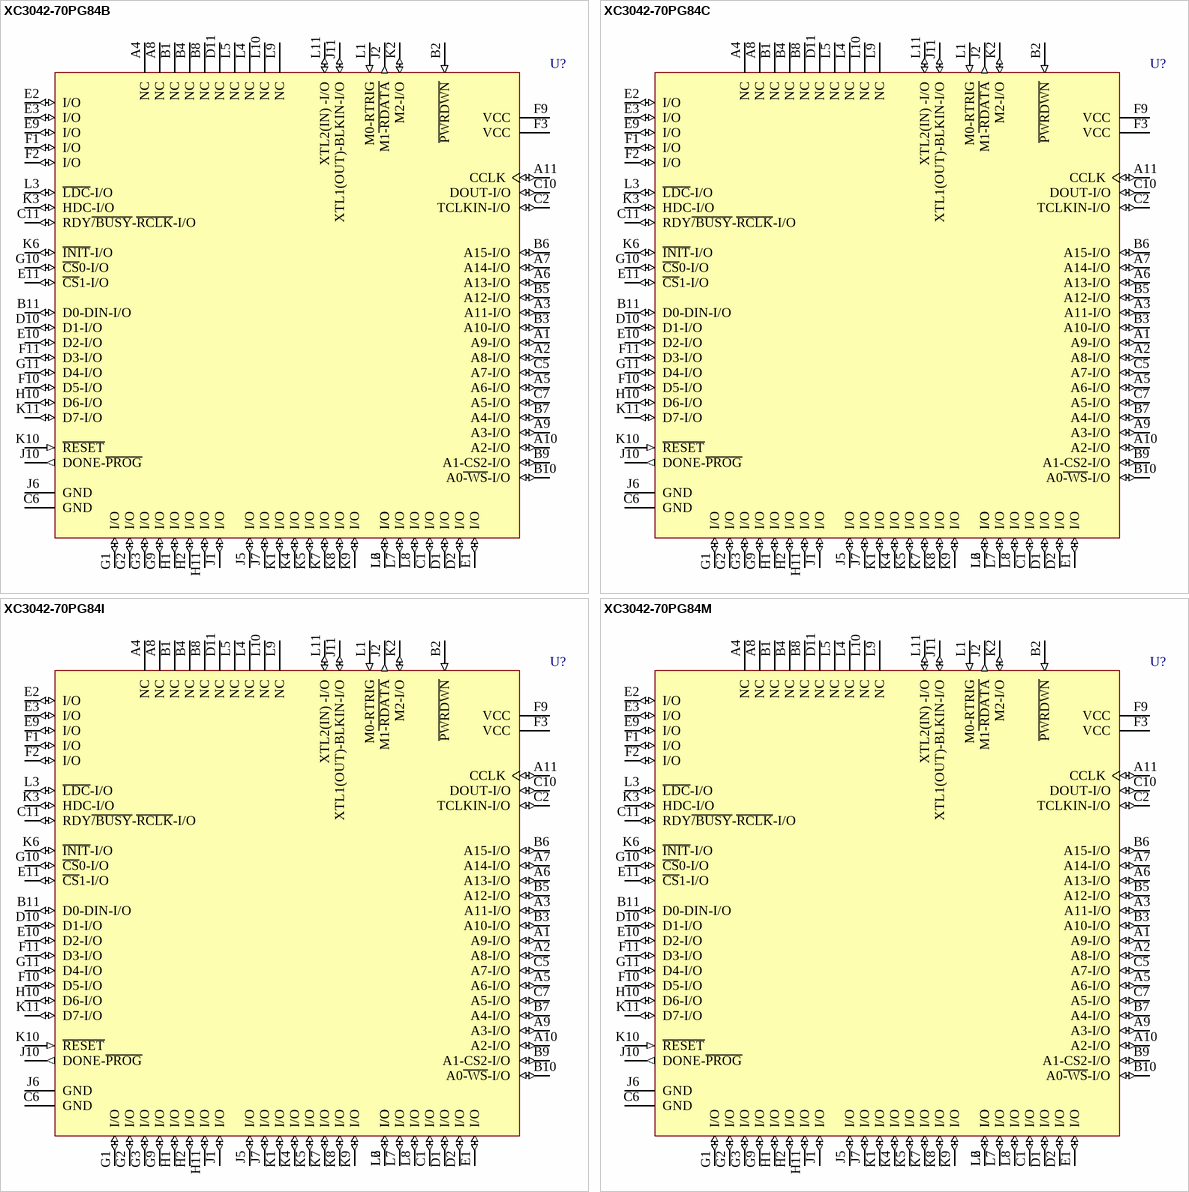
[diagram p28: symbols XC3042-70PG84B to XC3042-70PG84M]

## XC3042-70PG84B
designator U?
Logic Cell Array with 144 CLBs, with 64 I/O Pins, 84-Pin PGA, Military Class B Grade; ComponentAvailability: Not for New Design
footprint PG84 (PGA, 85-Leads, Body 28x28mm, Pitch 2.54mm)
3D model XC3042-PG84 (84-Pin Ceramic Pin Grid Array (PG84))
pins: A1 A9-I/O (io), A2 A8-I/O (io), A3 A11-I/O (io), A4 NC, A5 A6-I/O (io), A6 A13-I/O (io), A7 A14-I/O (io), A8 NC, A9 A3-I/O (io), A10 A2-I/O (io), A11 CCLK (io), B1 NC, B2 ~{PWRDWN} (in), B3 A10-I/O (io), B4 NC, B5 A12-I/O (io), B6 A15-I/O (io), B7 A4-I/O (io), B8 NC, B9 A1-CS2-I/O (io), B10 A0~{-WS}-I/O (io), B11 D0-DIN-I/O (io), C1 I/O (io), C2 TCLKIN-I/O (io), C5 A7-I/O (io), C6 GND (power), C7 A5-I/O (io), C10 DOUT-I/O (io), C11 RDY~{/BUSY}-~{RCLK}-I/O (io), D1 I/O (io), D2 I/O (io), D10 D1-I/O (io), D11 NC, E1 I/O (io), E2 I/O (io), E3 I/O (io), E9 I/O (io), E10 D2-I/O (io), E11 ~{CS}1-I/O (io), F1 I/O (io), F2 I/O (io), F3 VCC (power), F9 VCC (power), F10 D5-I/O (io), F11 D3-I/O (io), G1 I/O (io), G2 I/O (io), G3 I/O (io), G9 I/O (io), G10 ~{CS}0-I/O (io), G11 D4-I/O (io), H1 I/O (io), H2 I/O (io), H10 D6-I/O (io), H11 I/O (io), J1 I/O (io), J2 M1~{-RDATA} (out), J5 I/O (io), J6 GND (power), J7 I/O (io), J10 DONE-~{PROG} (out), J11 XTL1(OUT)-BLKIN-I/O (io), K1 I/O (io), K2 M2-I/O (io), K3 HDC-I/O (io), K4 I/O (io), K5 I/O (io), K6 ~{INIT}-I/O (io), K7 I/O (io), K8 I/O (io), K9 I/O (io), K10 ~{RESET} (in), K11 D7-I/O (io), L1 M0-RTRIG (in), L2 I/O (io), L3 ~{LDC}-I/O (io), L4 NC, L5 NC, L6 I/O (io), L7 I/O (io), L8 I/O (io), L9 NC, L10 NC, L11 XTL2(IN) -I/O (io)

## XC3042-70PG84C
designator U?
Logic Cell Array with 144 CLBs, with 64 I/O Pins, 84-Pin PGA, Commercial Grade; ComponentAvailability: Not for New Design
footprint PG84 (PGA, 85-Leads, Body 28x28mm, Pitch 2.54mm)
3D model XC3042-PG84 (84-Pin Ceramic Pin Grid Array (PG84))
pins: A1 A9-I/O (io), A2 A8-I/O (io), A3 A11-I/O (io), A4 NC, A5 A6-I/O (io), A6 A13-I/O (io), A7 A14-I/O (io), A8 NC, A9 A3-I/O (io), A10 A2-I/O (io), A11 CCLK (io), B1 NC, B2 ~{PWRDWN} (in), B3 A10-I/O (io), B4 NC, B5 A12-I/O (io), B6 A15-I/O (io), B7 A4-I/O (io), B8 NC, B9 A1-CS2-I/O (io), B10 A0~{-WS}-I/O (io), B11 D0-DIN-I/O (io), C1 I/O (io), C2 TCLKIN-I/O (io), C5 A7-I/O (io), C6 GND (power), C7 A5-I/O (io), C10 DOUT-I/O (io), C11 RDY~{/BUSY}-~{RCLK}-I/O (io), D1 I/O (io), D2 I/O (io), D10 D1-I/O (io), D11 NC, E1 I/O (io), E2 I/O (io), E3 I/O (io), E9 I/O (io), E10 D2-I/O (io), E11 ~{CS}1-I/O (io), F1 I/O (io), F2 I/O (io), F3 VCC (power), F9 VCC (power), F10 D5-I/O (io), F11 D3-I/O (io), G1 I/O (io), G2 I/O (io), G3 I/O (io), G9 I/O (io), G10 ~{CS}0-I/O (io), G11 D4-I/O (io), H1 I/O (io), H2 I/O (io), H10 D6-I/O (io), H11 I/O (io), J1 I/O (io), J2 M1~{-RDATA} (out), J5 I/O (io), J6 GND (power), J7 I/O (io), J10 DONE-~{PROG} (out), J11 XTL1(OUT)-BLKIN-I/O (io), K1 I/O (io), K2 M2-I/O (io), K3 HDC-I/O (io), K4 I/O (io), K5 I/O (io), K6 ~{INIT}-I/O (io), K7 I/O (io), K8 I/O (io), K9 I/O (io), K10 ~{RESET} (in), K11 D7-I/O (io), L1 M0-RTRIG (in), L2 I/O (io), L3 ~{LDC}-I/O (io), L4 NC, L5 NC, L6 I/O (io), L7 I/O (io), L8 I/O (io), L9 NC, L10 NC, L11 XTL2(IN) -I/O (io)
